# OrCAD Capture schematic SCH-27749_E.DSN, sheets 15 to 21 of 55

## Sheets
15 2V5 & PHY 1V8 Power: size C
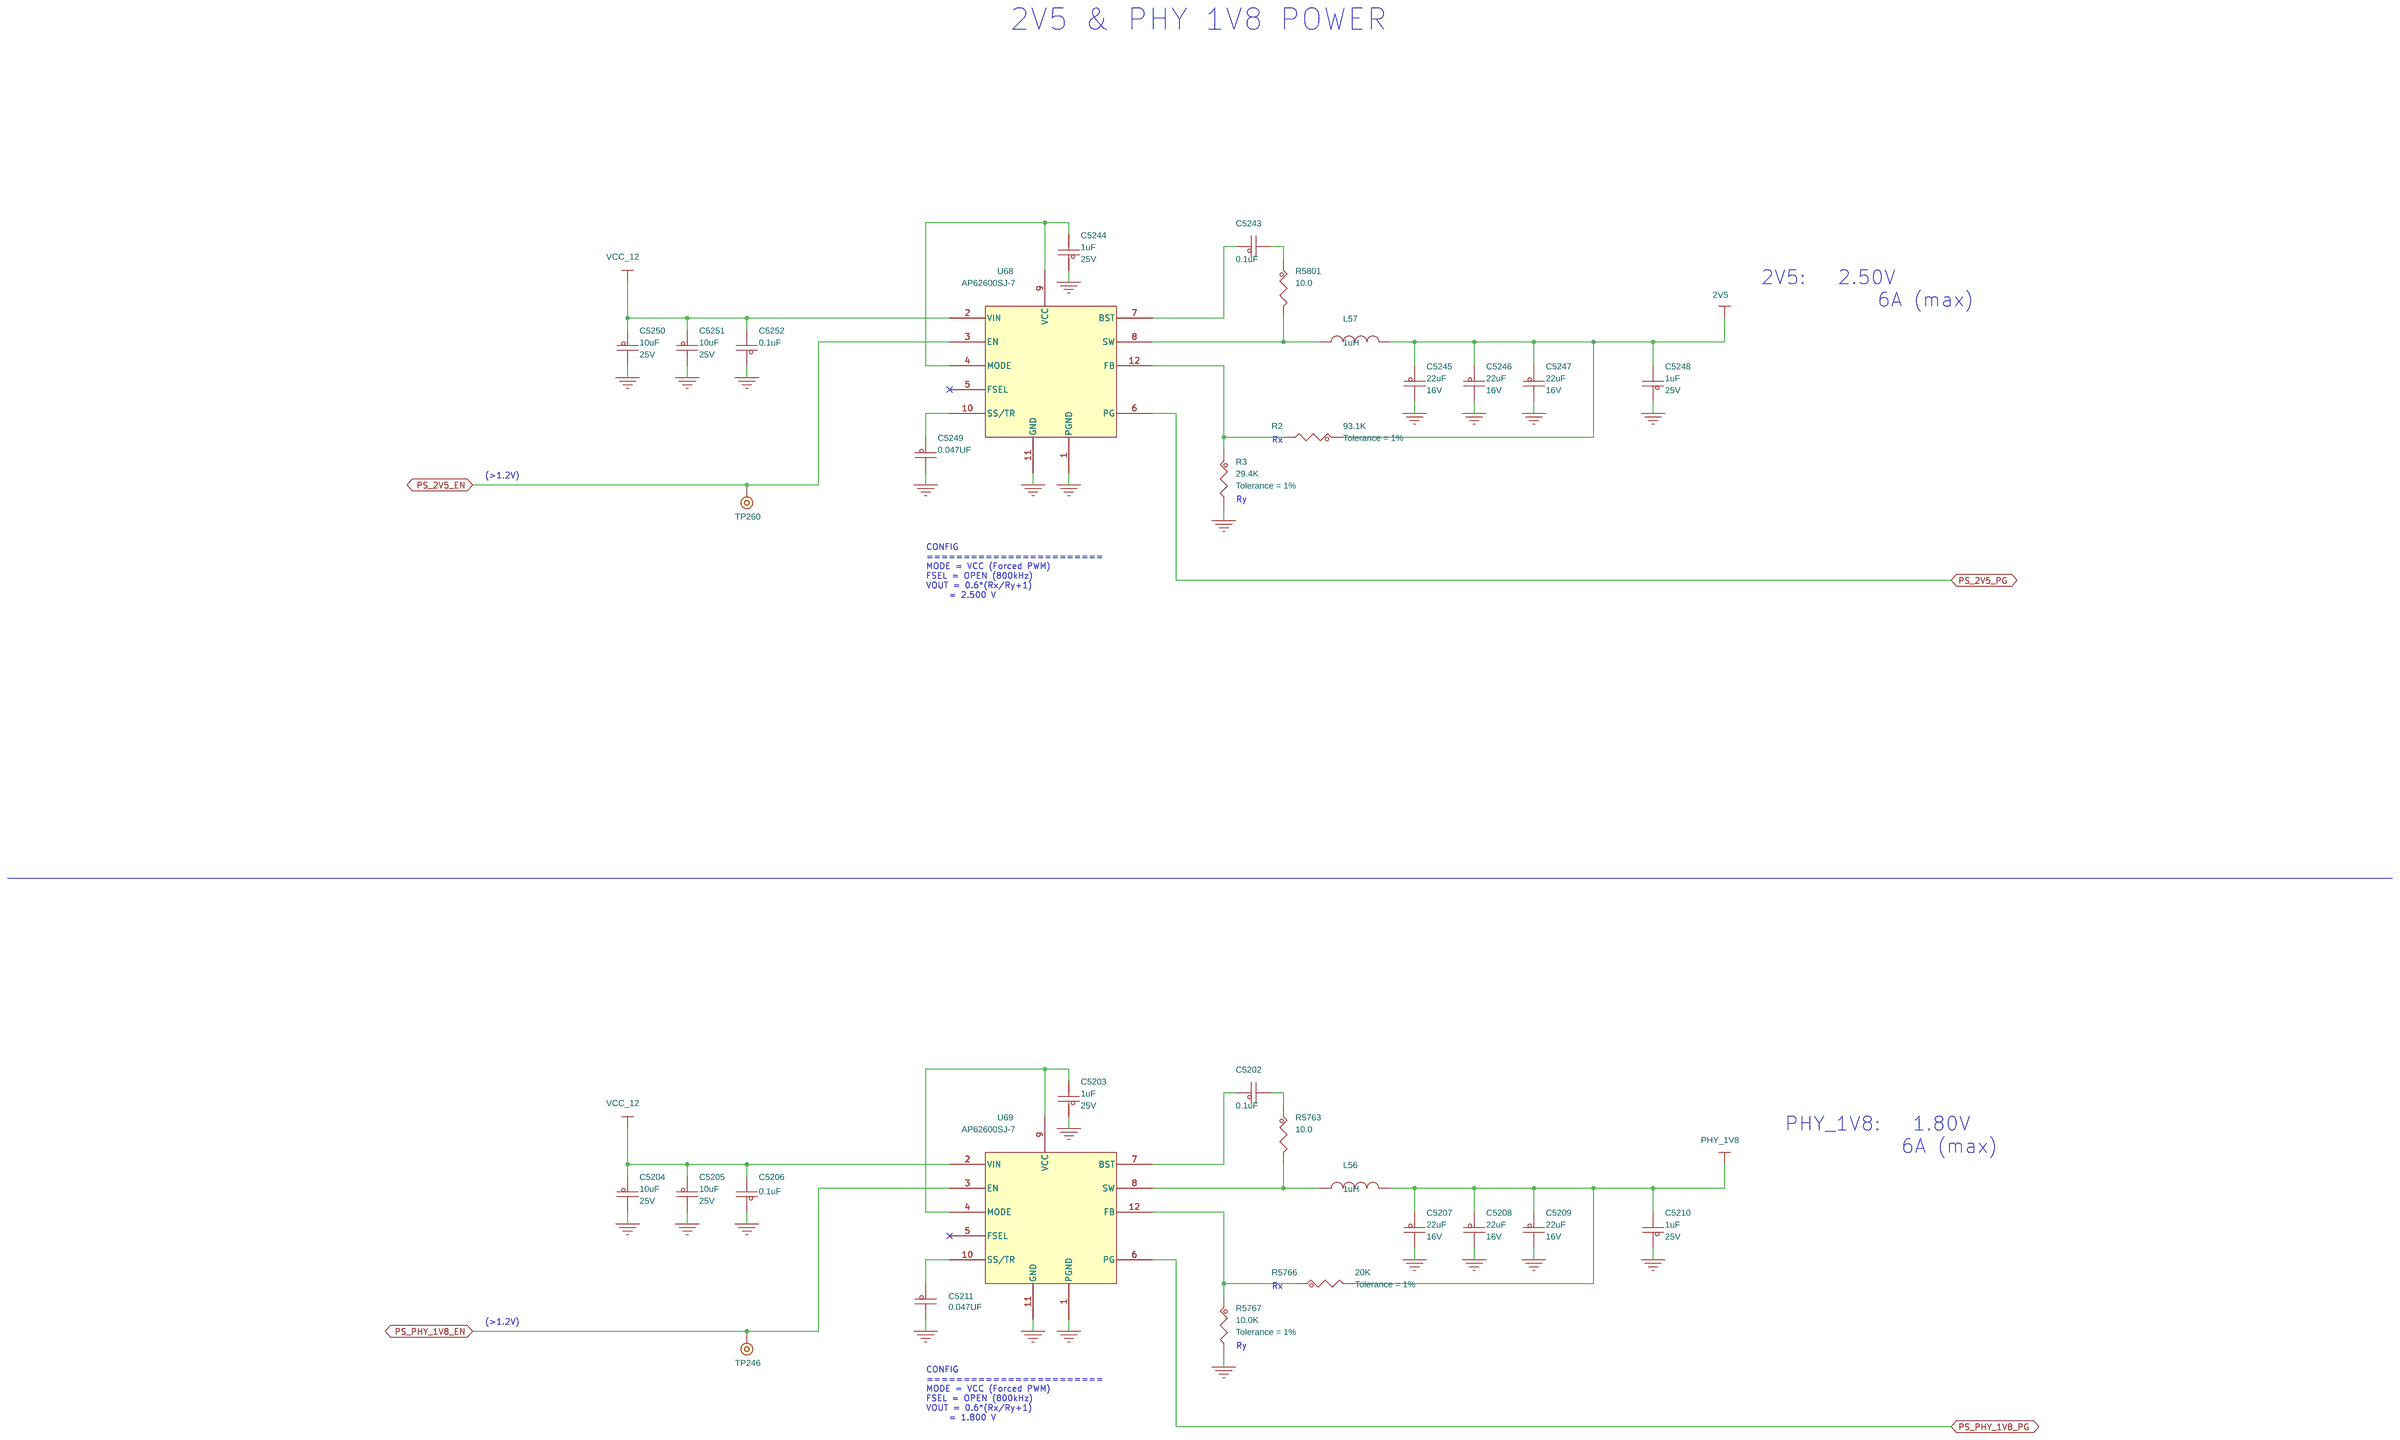
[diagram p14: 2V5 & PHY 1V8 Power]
16 Misc Power: size C
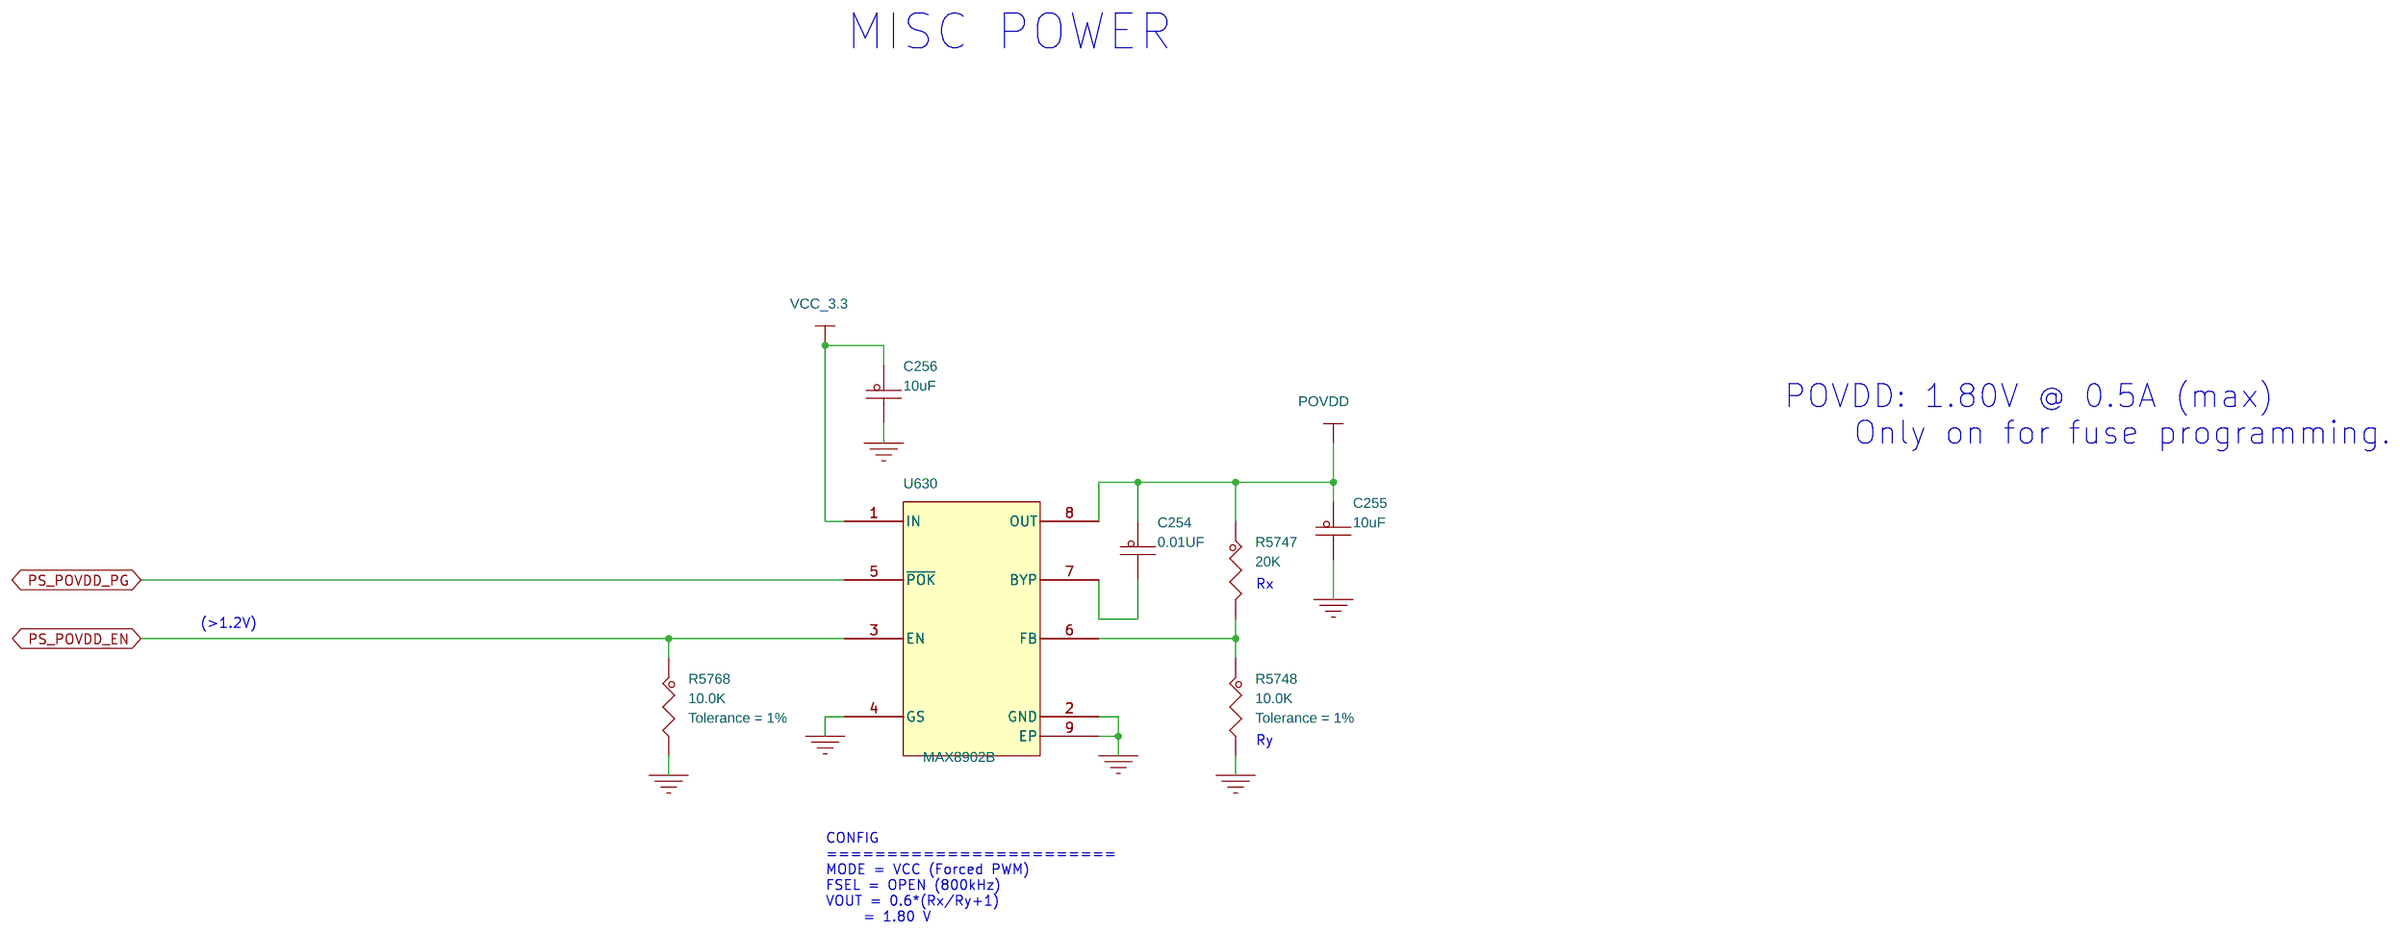
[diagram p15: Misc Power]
17 reserved
18 T4240 VDD Power: size C
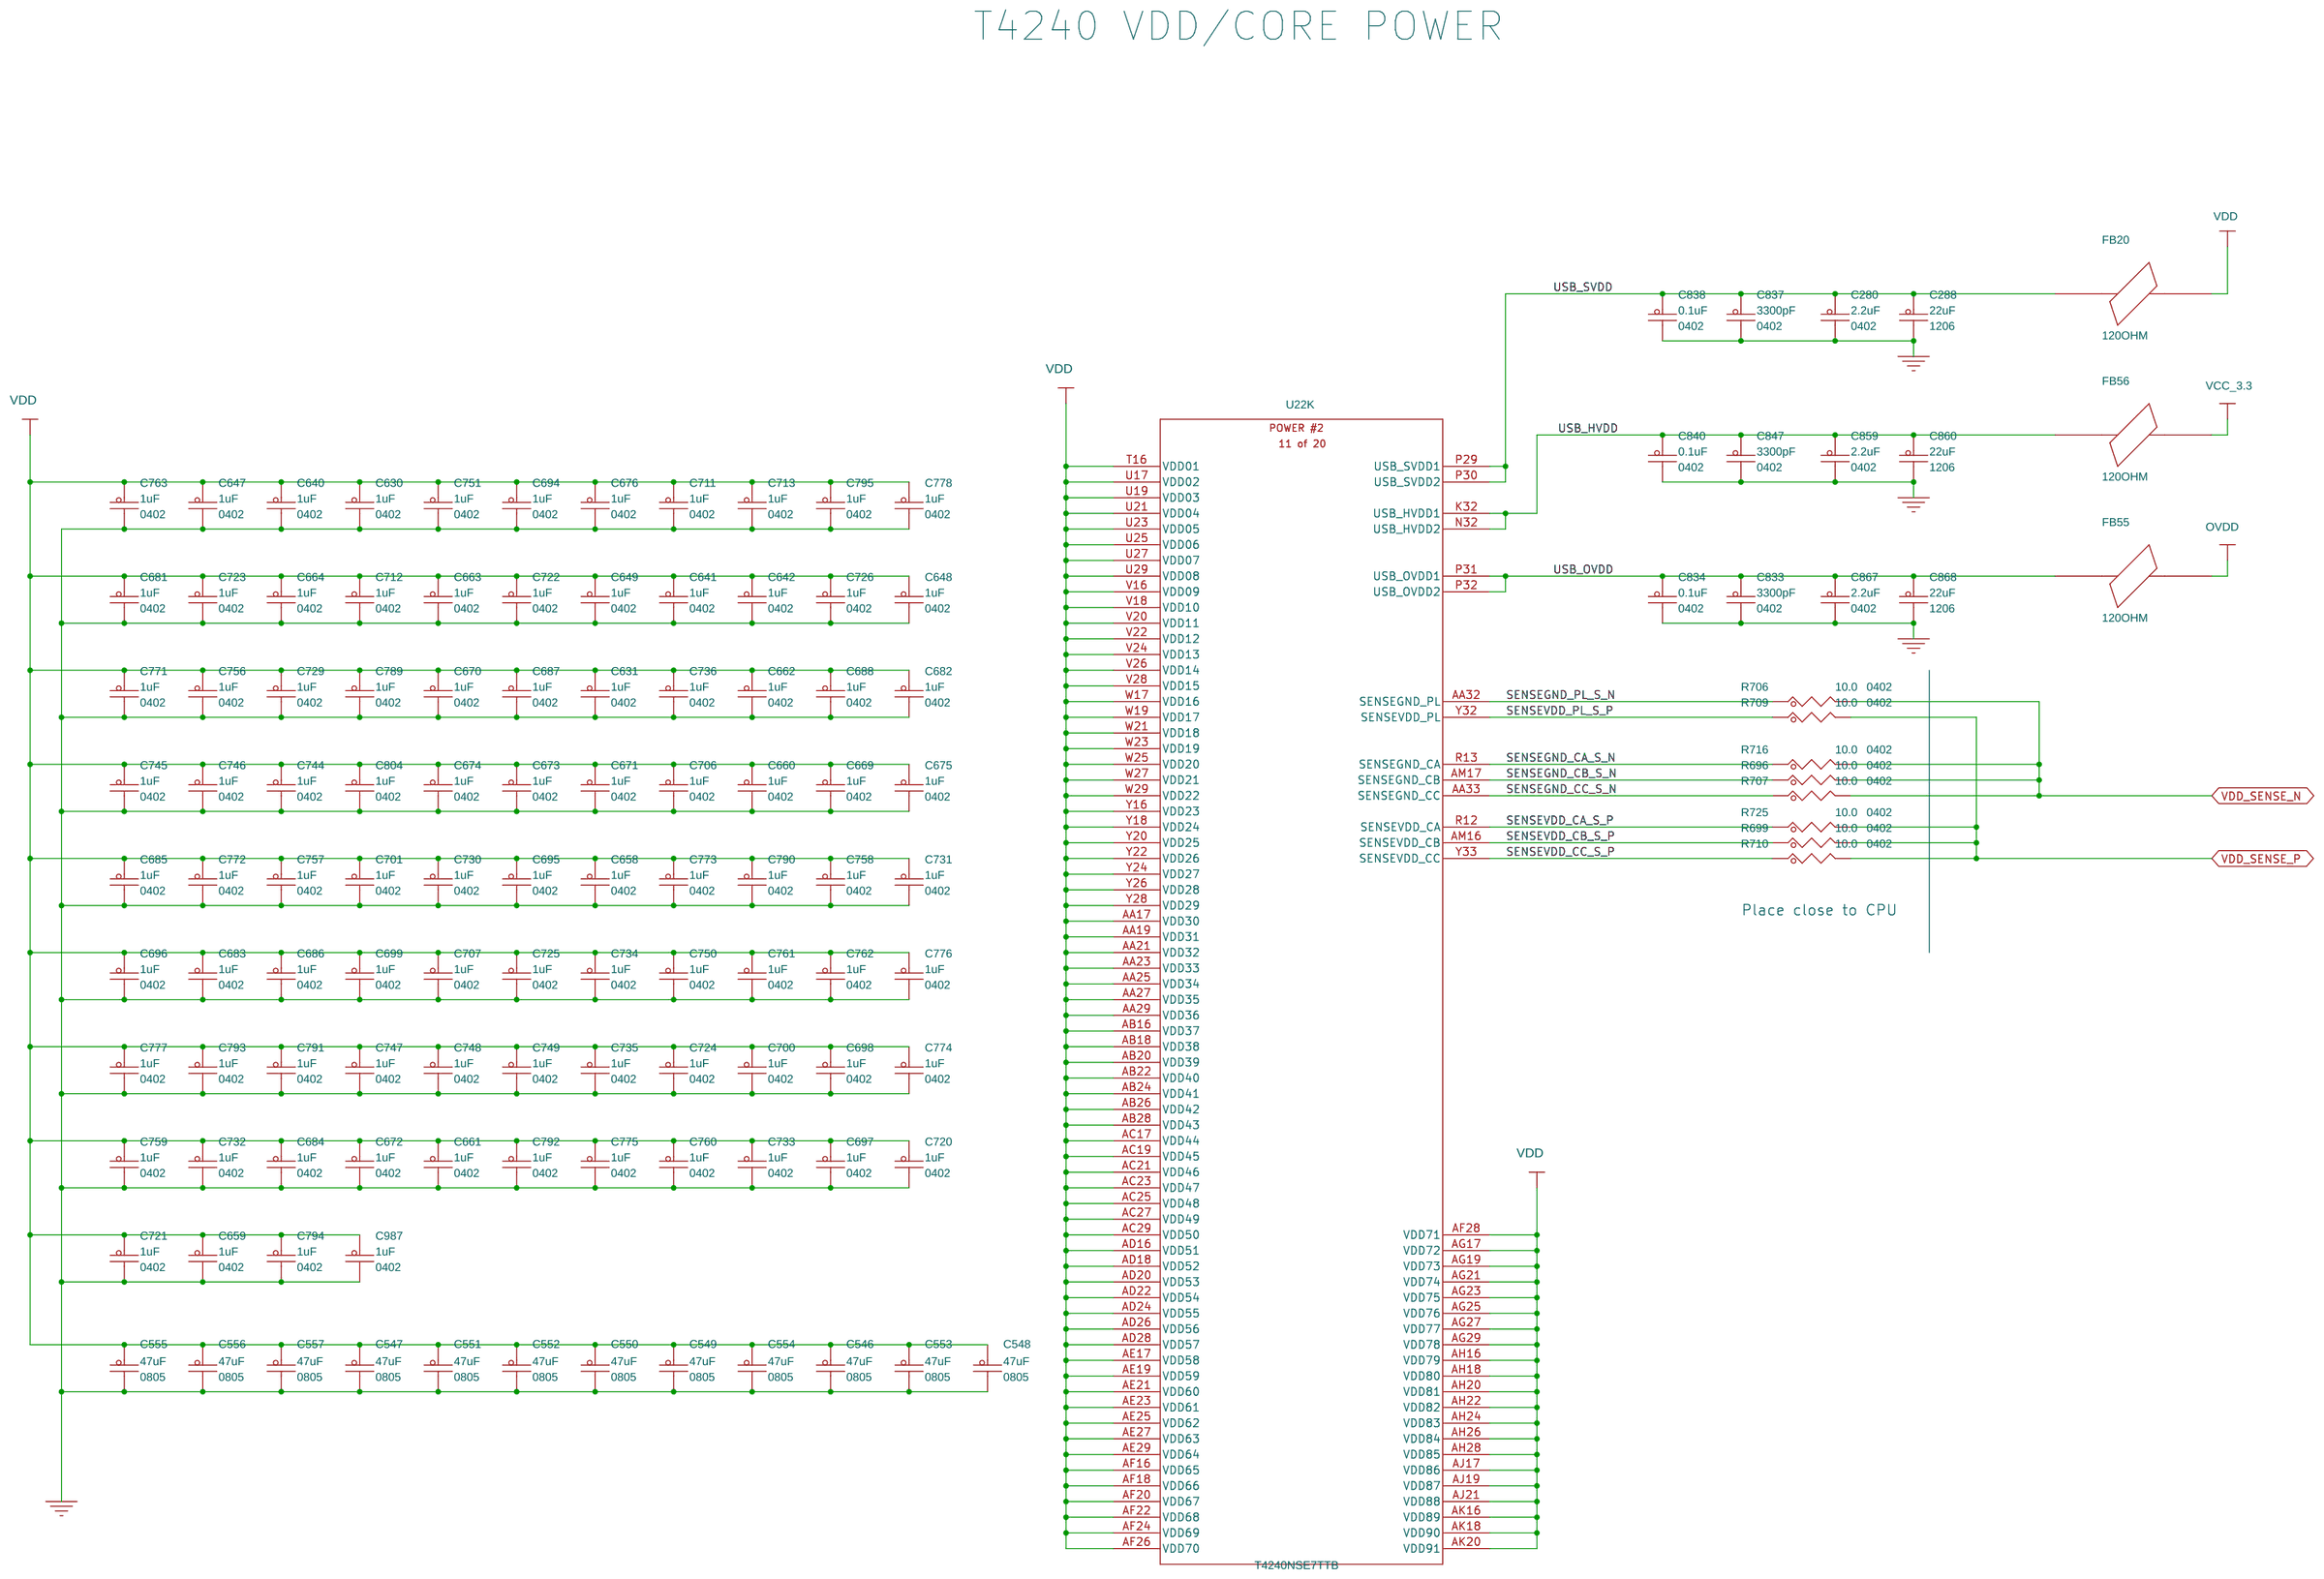
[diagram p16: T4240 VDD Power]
19 T4240 SVDD/XVDD Power: size C
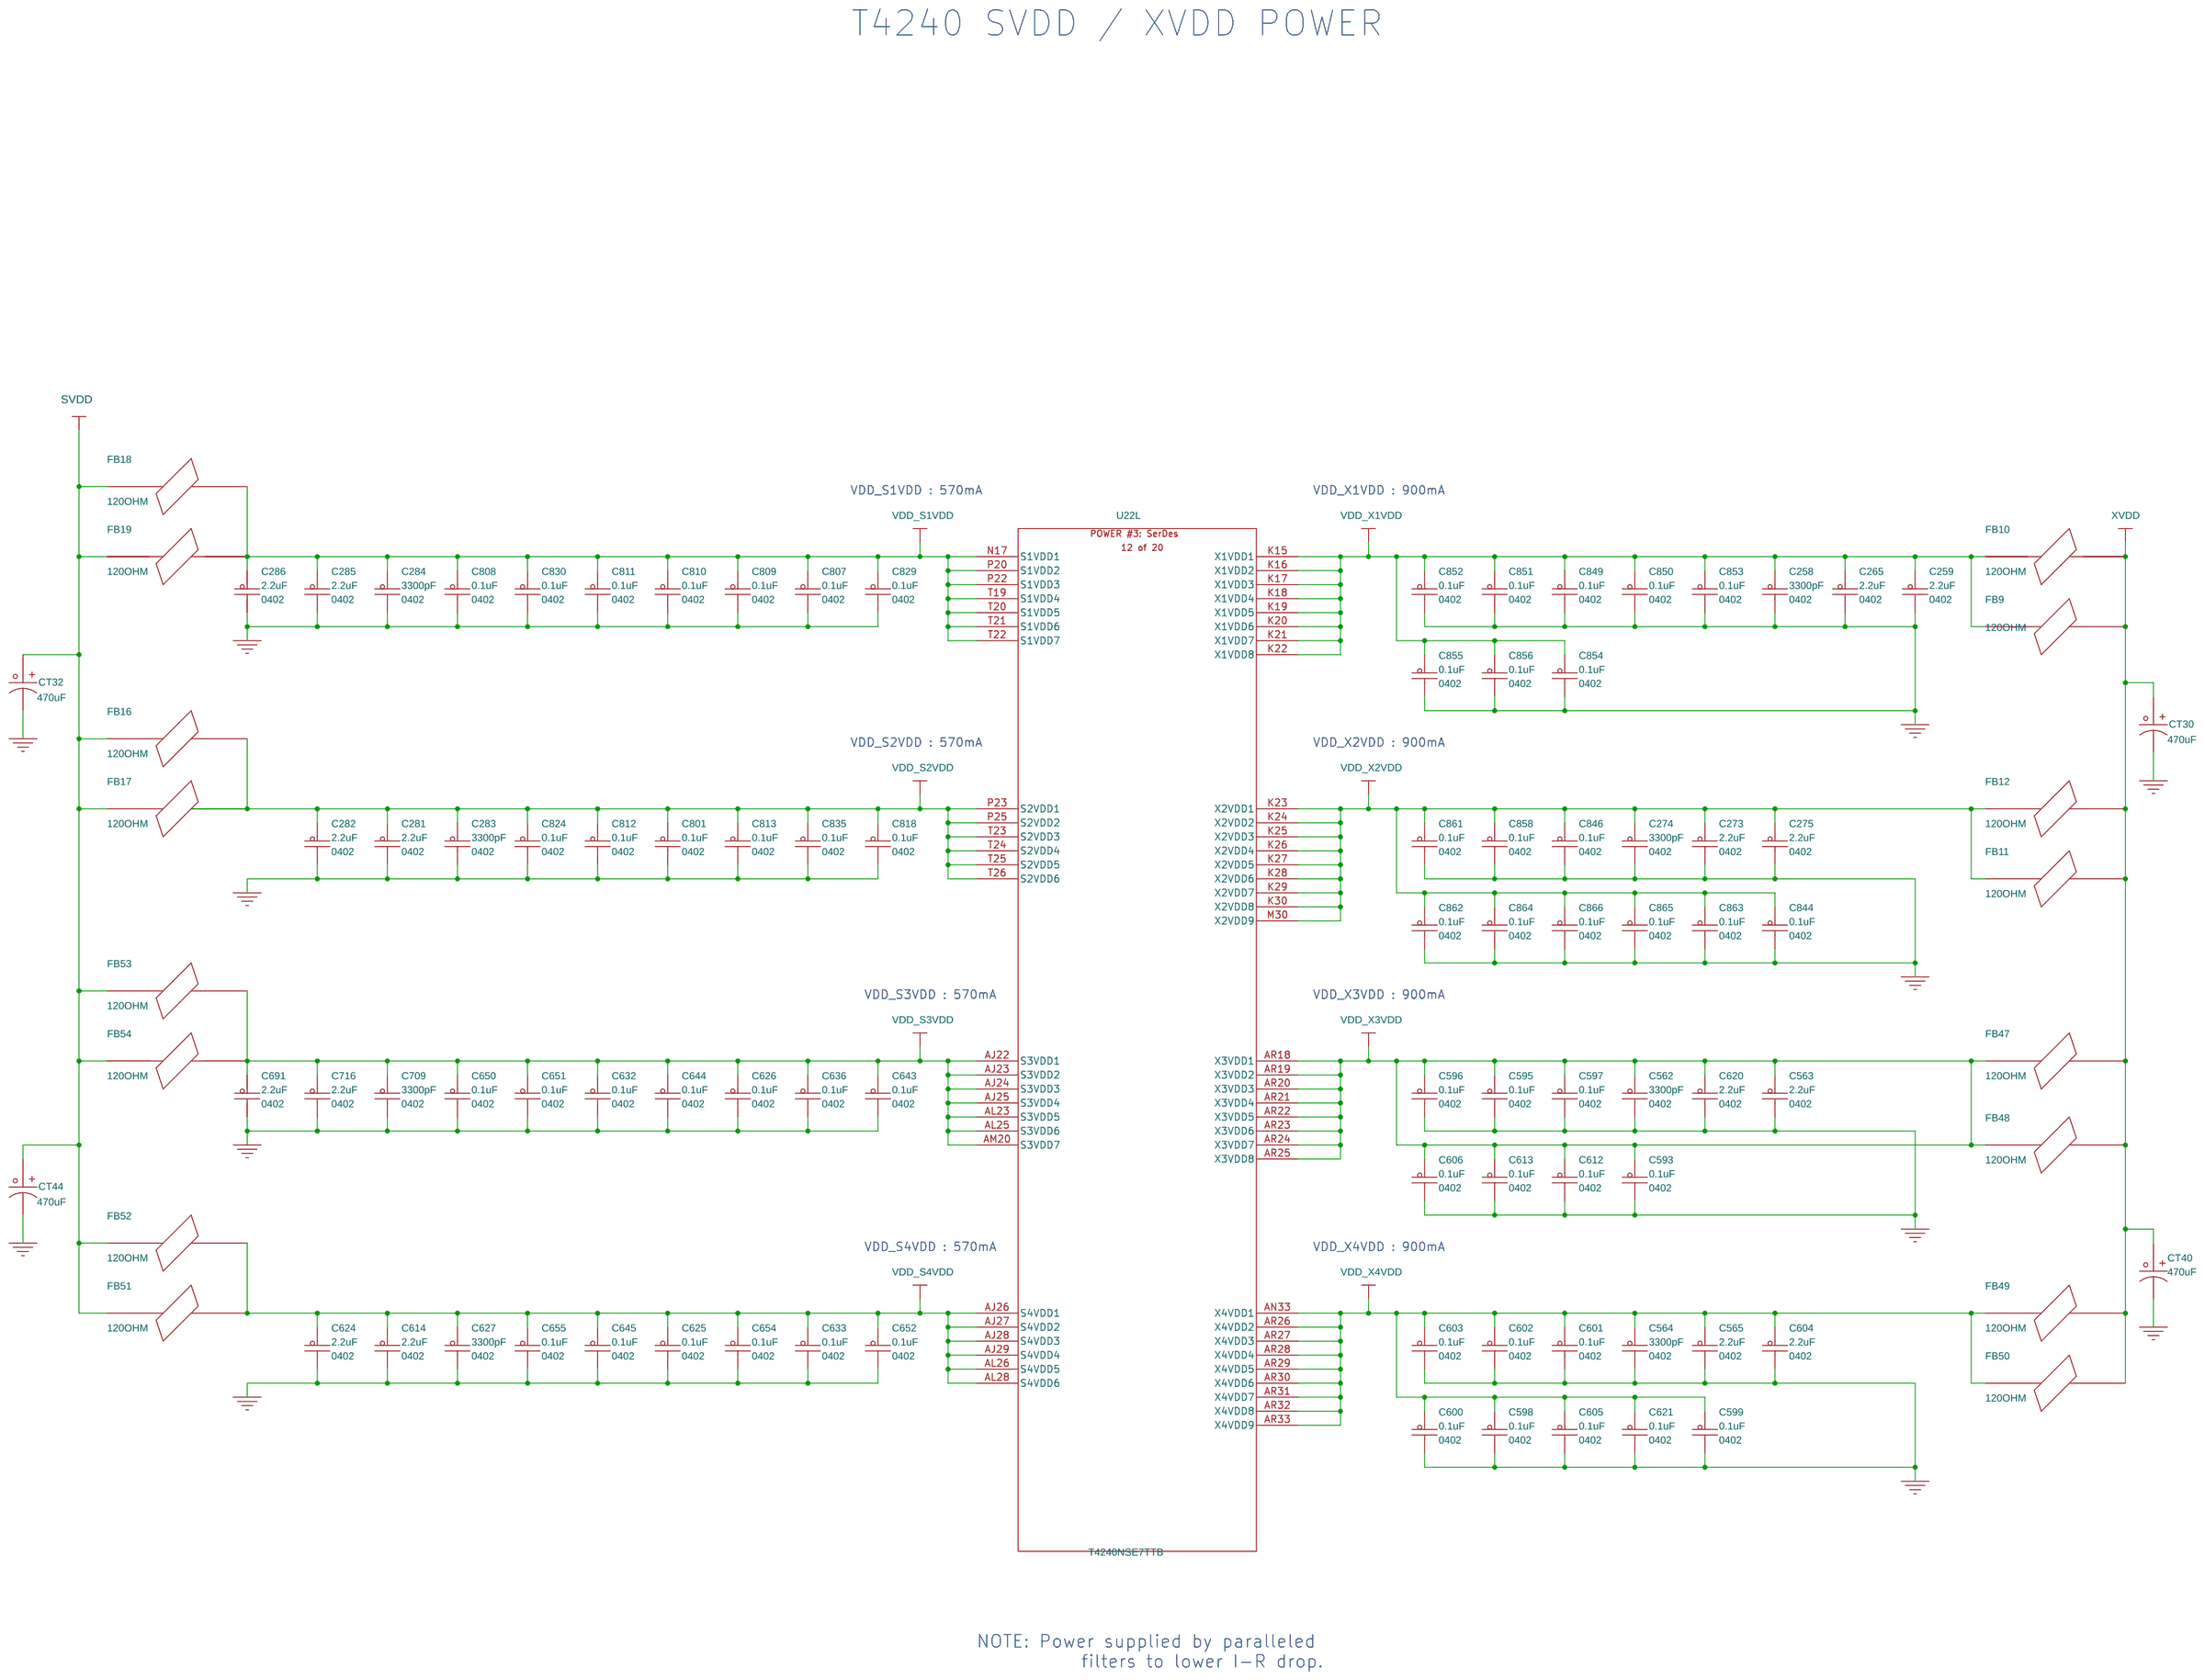
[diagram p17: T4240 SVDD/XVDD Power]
20 T4240 GVDD+Other Power: size C
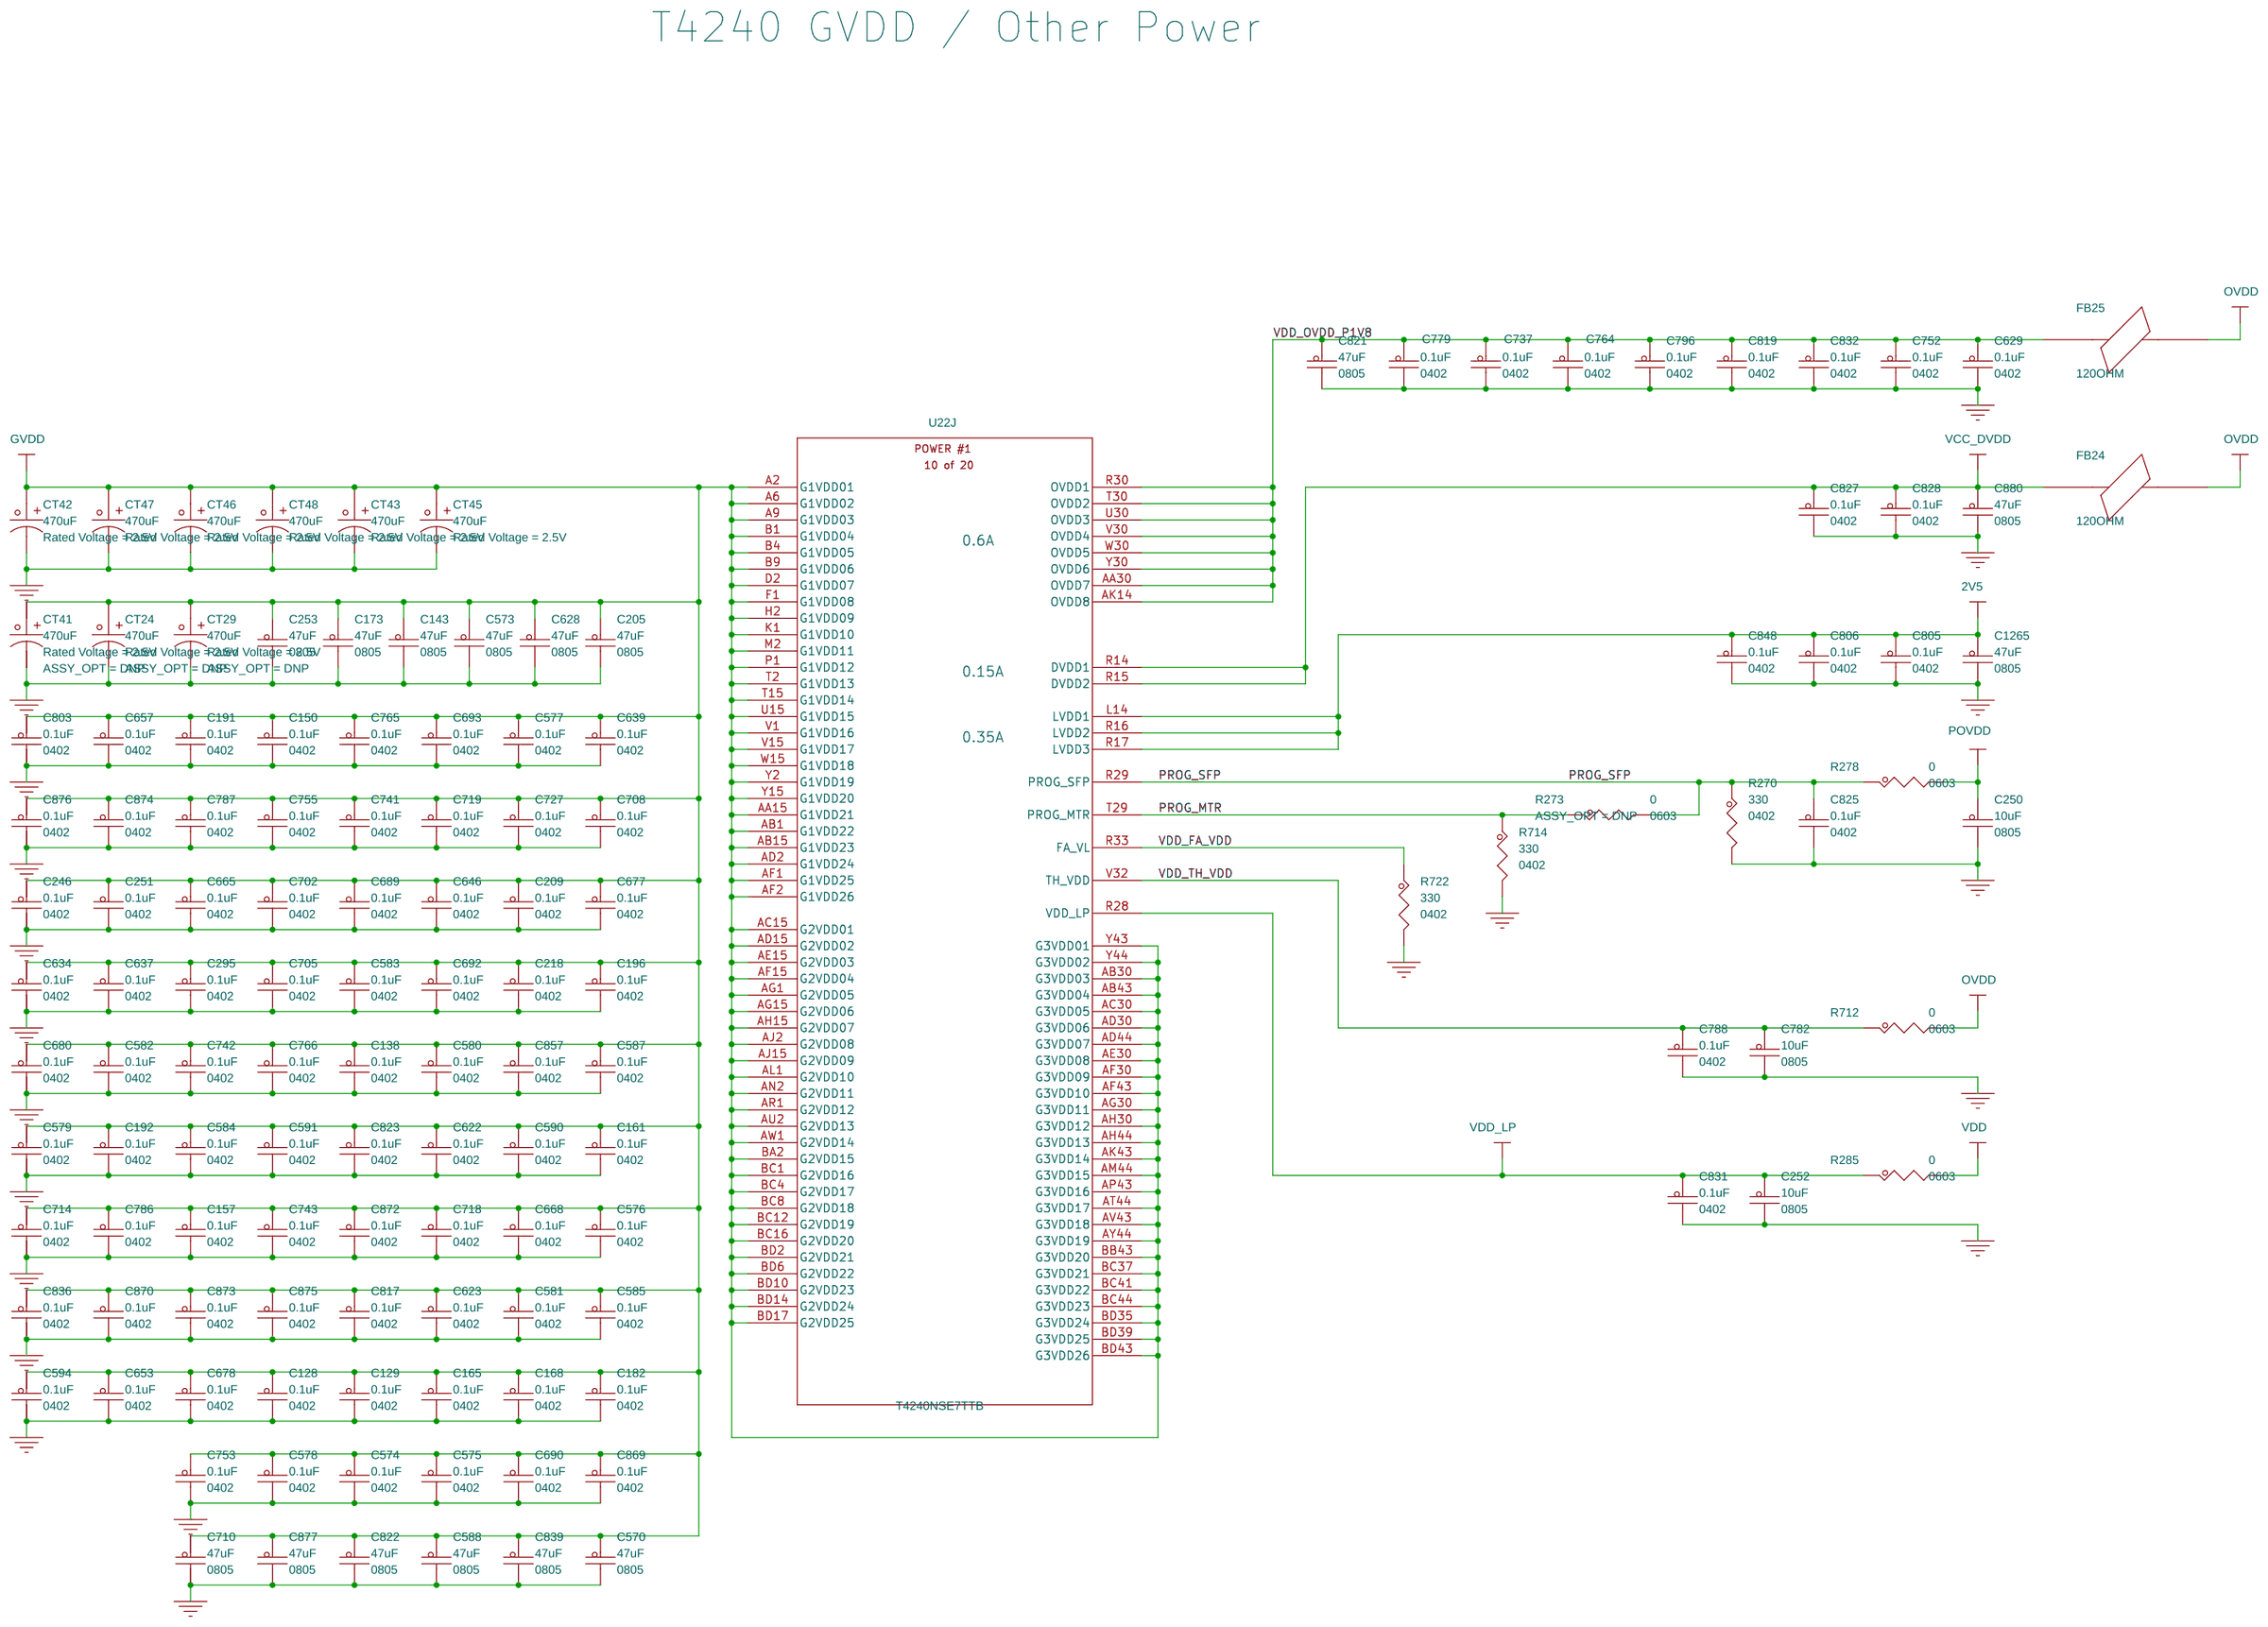
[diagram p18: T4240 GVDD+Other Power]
21 T4240 PLL Filters: size C
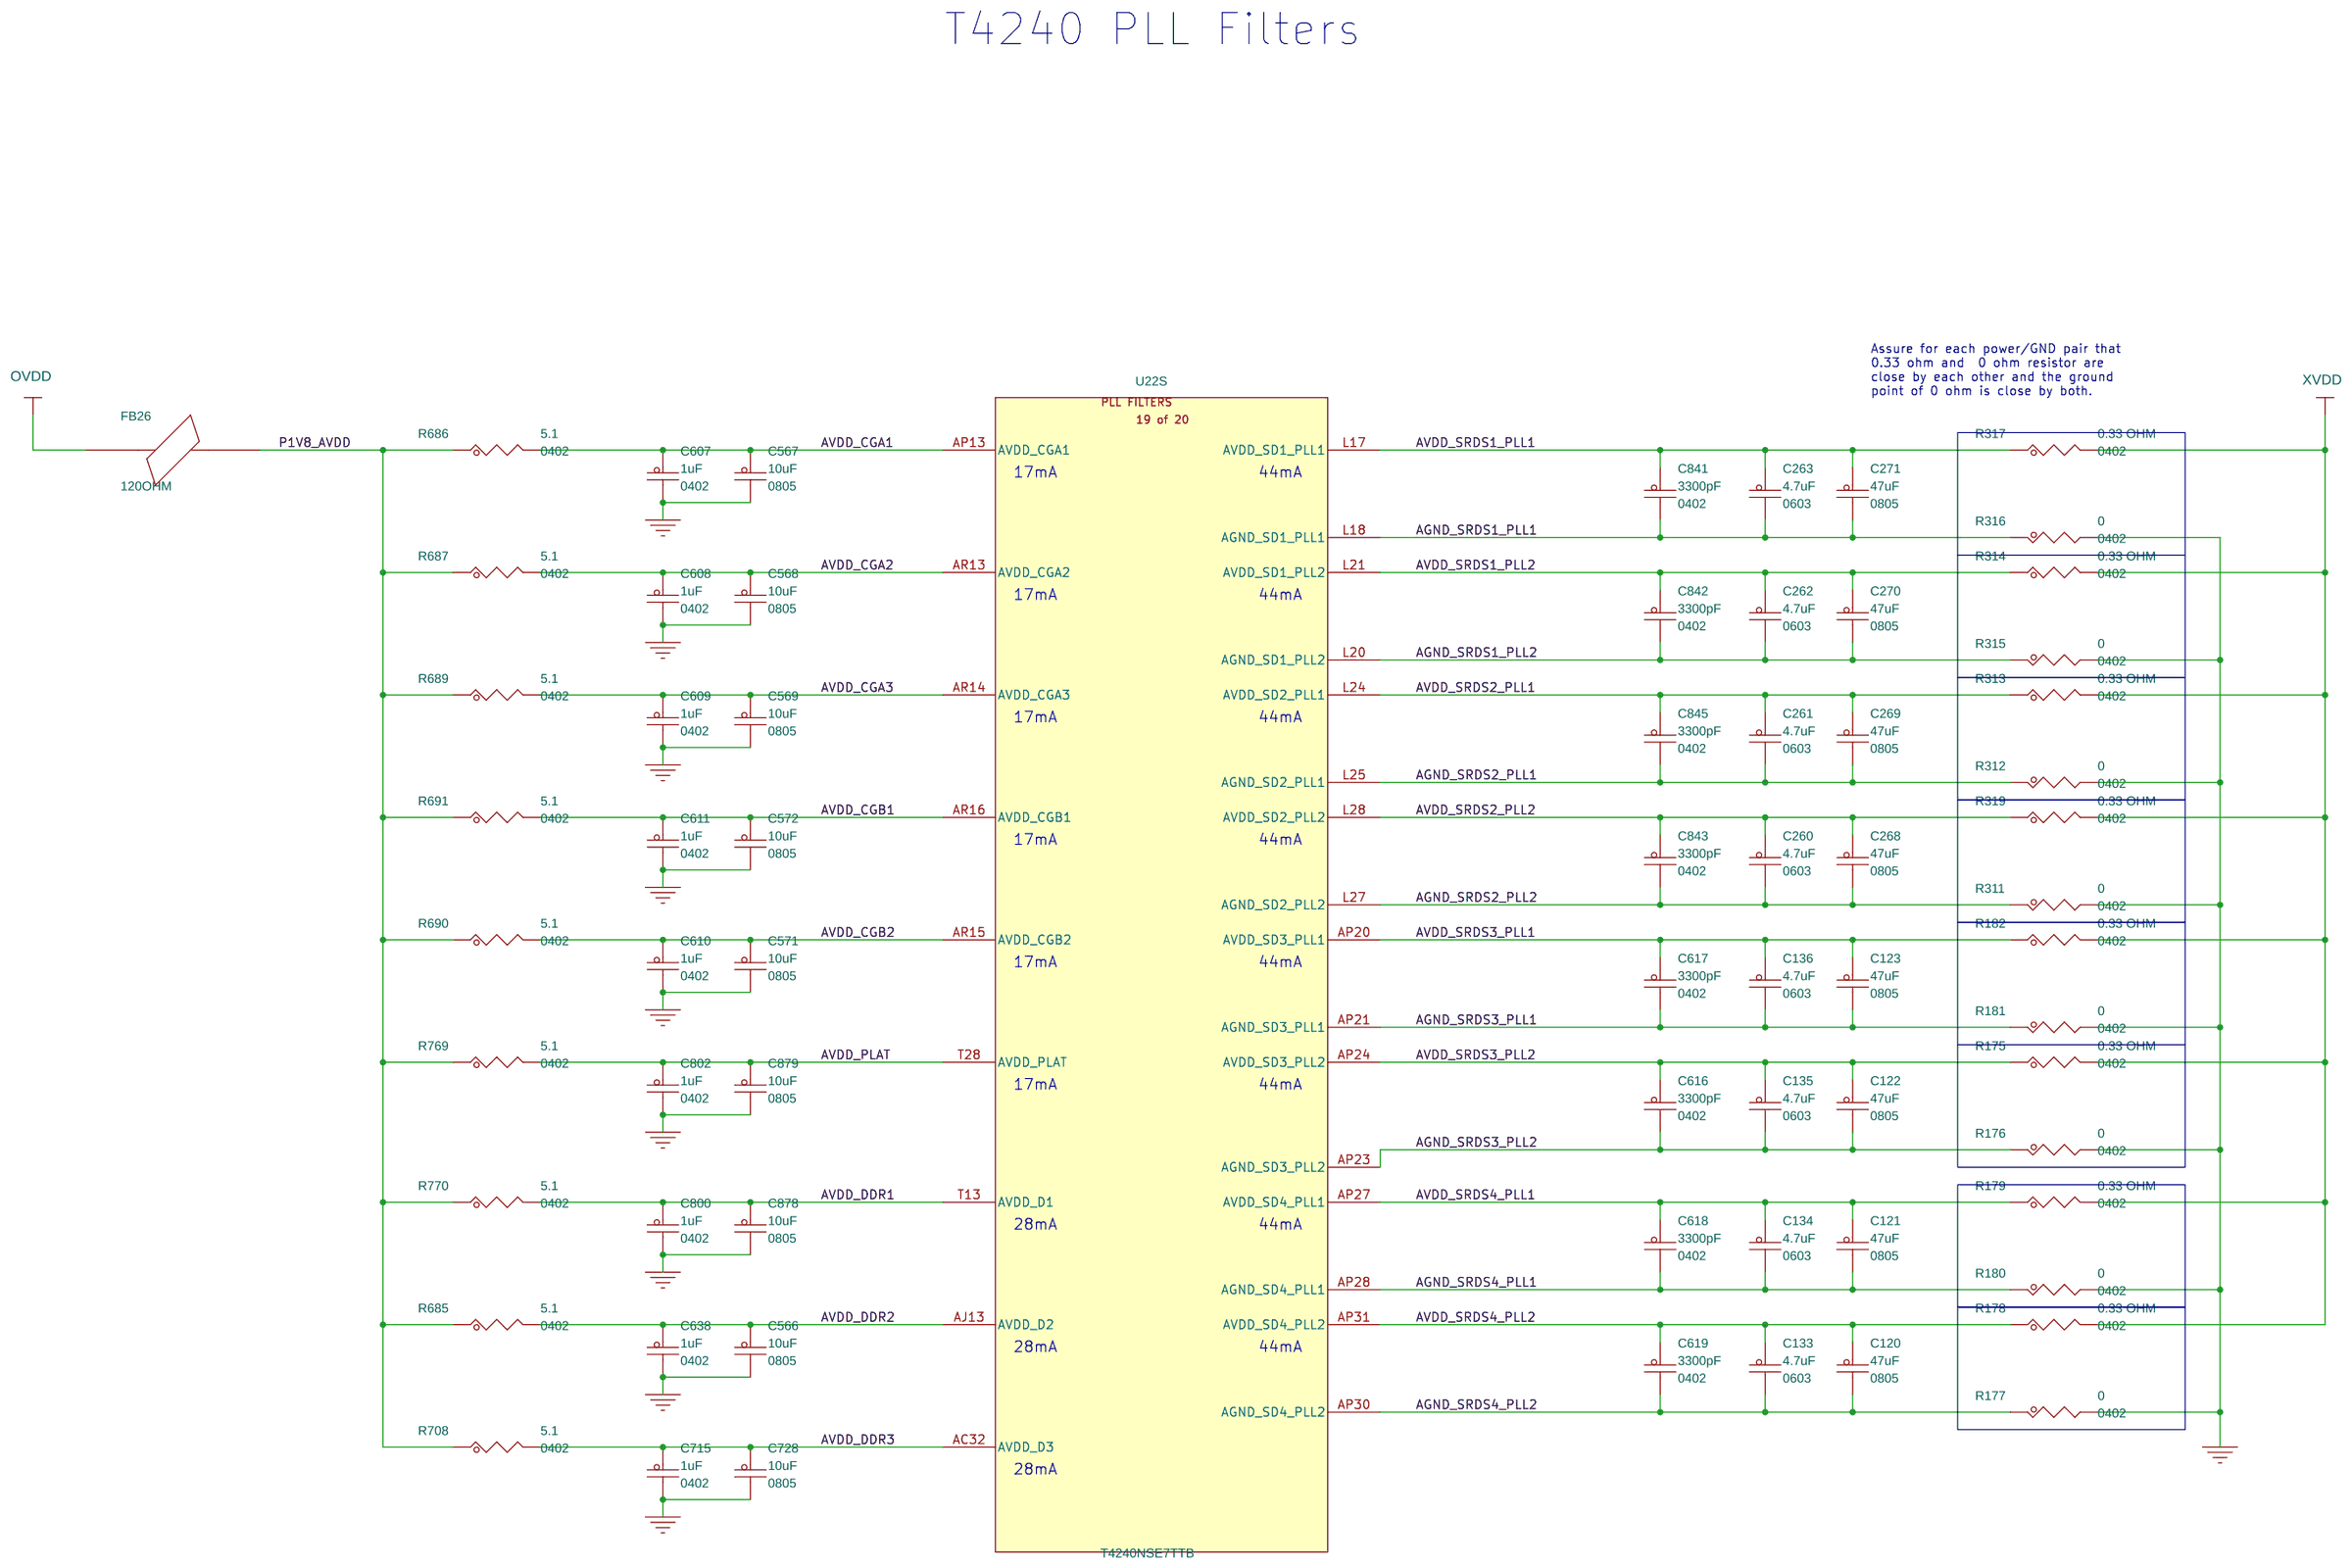
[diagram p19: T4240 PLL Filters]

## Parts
sheet 2V5 & PHY 1V8 Power
C5202  0.1uF  [CC0402_HD]
C5203  1uF  [CC0603_OV]
C5204  10uF  [CC1206_OV]
C5205  10uF  [CC1206_OV]
C5206  0.1uF  [CC0402_HD]
C5207  22uF  [1206_CC]
C5208  22uF  [1206_CC]
C5209  22uF  [1206_CC]
C5210  1uF  [CC0603_OV]
C5211  0.047UF  [CC0603_OV]
C5243  0.1uF  [CC0402_HD]
C5244  1uF  [CC0603_OV]
C5245  22uF  [1206_CC]
C5246  22uF  [1206_CC]
C5247  22uF  [1206_CC]
C5248  1uF  [CC0603_OV]
C5249  0.047UF  [CC0603_OV]
C5250  10uF  [CC1206_OV]
C5251  10uF  [CC1206_OV]
C5252  0.1uF  [CC0402_HD]
L56  1uH  [ind2_sq6p9_3_sm]
L57  1uH  [ind2_sq6p9_3_sm]
R2  93.1K  [RC0402_25]
R3  29.4K  [RC0402_25]
R5763  10.0  [RC0402_25]
R5766  20K  [RC0402_25]
R5767  10.0K  [RC0402_25]
R5801  10.0  [RC0402_25]
TP246  TPAD_020  [tpad_020_top]
TP260  TPAD_020  [tpad_020_top]
U68  AP62600SJ-7  [qfn12_0p5_2p05x3p05mm]
U69  AP62600SJ-7  [qfn12_0p5_2p05x3p05mm]
sheet Misc Power
C254  0.01UF  [CC0402_HD]
C255  10uF  [CC0603_OV]
C256  10uF  [CC0603_OV]
R5747  20K  [RC0402_25]
R5748  10.0K  [RC0402_25]
R5768  10.0K  [RC0402_25]
U630  MAX8902B  [tdfn8_1p98_2p10x2p10]
sheet T4240 DDR Controller #2
U22  T4240NSE7TTB  [BGA1932_1MM_45X45MM]  (sections A,B,C,D,E,F,G,H,I,J,K,L,M,N,O,P,Q,R,S,T)
sheet T4240 GVDD+Other Power
C128  0.1uF  [CC0402_HD]
C129  0.1uF  [CC0402_HD]
C138  0.1uF  [CC0402_HD]
C143  47uF  [CC0805_OV]
C150  0.1uF  [CC0402_HD]
C157  0.1uF  [CC0402_HD]
C161  0.1uF  [CC0402_HD]
C165  0.1uF  [CC0402_HD]
C168  0.1uF  [CC0402_HD]
C173  47uF  [CC0805_OV]
C182  0.1uF  [CC0402_HD]
C191  0.1uF  [CC0402_HD]
C192  0.1uF  [CC0402_HD]
C196  0.1uF  [CC0402_HD]
C205  47uF  [CC0805_OV]
C209  0.1uF  [CC0402_HD]
C218  0.1uF  [CC0402_HD]
C246  0.1uF  [CC0402_HD]
C250  10uF  [CC0603_OV]
C251  0.1uF  [CC0402_HD]
C252  10uF  [CC0603_OV]
C253  47uF  [CC0805_OV]
C295  0.1uF  [CC0402_HD]
C570  47uF  [CC0805_OV]
C573  47uF  [CC0805_OV]
C574  0.1uF  [CC0402_HD]
C575  0.1uF  [CC0402_HD]
C576  0.1uF  [CC0402_HD]
C577  0.1uF  [CC0402_HD]
C578  0.1uF  [CC0402_HD]
C579  0.1uF  [CC0402_HD]
C580  0.1uF  [CC0402_HD]
C581  0.1uF  [CC0402_HD]
C582  0.1uF  [CC0402_HD]
C583  0.1uF  [CC0402_HD]
C584  0.1uF  [CC0402_HD]
C585  0.1uF  [CC0402_HD]
C587  0.1uF  [CC0402_HD]
C588  47uF  [CC0805_OV]
C590  0.1uF  [CC0402_HD]
C591  0.1uF  [CC0402_HD]
C594  0.1uF  [CC0402_HD]
C622  0.1uF  [CC0402_HD]
C623  0.1uF  [CC0402_HD]
C628  47uF  [CC0805_OV]
C629  0.1uF  [CC0402_HD]
C634  0.1uF  [CC0402_HD]
C637  0.1uF  [CC0402_HD]
C639  0.1uF  [CC0402_HD]
C646  0.1uF  [CC0402_HD]
C653  0.1uF  [CC0402_HD]
C657  0.1uF  [CC0402_HD]
C665  0.1uF  [CC0402_HD]
C668  0.1uF  [CC0402_HD]
C677  0.1uF  [CC0402_HD]
C678  0.1uF  [CC0402_HD]
C680  0.1uF  [CC0402_HD]
C689  0.1uF  [CC0402_HD]
C690  0.1uF  [CC0402_HD]
C692  0.1uF  [CC0402_HD]
C693  0.1uF  [CC0402_HD]
C702  0.1uF  [CC0402_HD]
C705  0.1uF  [CC0402_HD]
C708  0.1uF  [CC0402_HD]
C710  47uF  [CC0805_OV]
C714  0.1uF  [CC0402_HD]
C718  0.1uF  [CC0402_HD]
C719  0.1uF  [CC0402_HD]
C727  0.1uF  [CC0402_HD]
C737  0.1uF  [CC0402_HD]
C741  0.1uF  [CC0402_HD]
C742  0.1uF  [CC0402_HD]
C743  0.1uF  [CC0402_HD]
C752  0.1uF  [CC0402_HD]
C753  0.1uF  [CC0402_HD]
C755  0.1uF  [CC0402_HD]
C764  0.1uF  [CC0402_HD]
C765  0.1uF  [CC0402_HD]
C766  0.1uF  [CC0402_HD]
C779  0.1uF  [CC0402_HD]
C782  10uF  [CC0603_OV]
C786  0.1uF  [CC0402_HD]
C787  0.1uF  [CC0402_HD]
C788  0.1uF  [CC0402_HD]
C796  0.1uF  [CC0402_HD]
C803  0.1uF  [CC0402_HD]
C805  0.1uF  [CC0402_HD]
C806  0.1uF  [CC0402_HD]
C817  0.1uF  [CC0402_HD]
C819  0.1uF  [CC0402_HD]
C821  47uF  [CC0805_OV]
C822  47uF  [CC0805_OV]
C823  0.1uF  [CC0402_HD]
C825  0.1uF  [CC0402_HD]
C827  0.1uF  [CC0402_HD]
C828  0.1uF  [CC0402_HD]
C831  0.1uF  [CC0402_HD]
C832  0.1uF  [CC0402_HD]
C836  0.1uF  [CC0402_HD]
C839  47uF  [CC0805_OV]
C848  0.1uF  [CC0402_HD]
C857  0.1uF  [CC0402_HD]
C869  0.1uF  [CC0402_HD]
C870  0.1uF  [CC0402_HD]
C872  0.1uF  [CC0402_HD]
C873  0.1uF  [CC0402_HD]
C874  0.1uF  [CC0402_HD]
C875  0.1uF  [CC0402_HD]
C876  0.1uF  [CC0402_HD]
C877  47uF  [CC0805_OV]
C880  47uF  [CC0805_OV]
C1265  47uF  [CC0805_OV]
CT24  470uF  [CC7343A]
CT29  470uF  [CC7343A]
CT41  470uF  [CC7343A]
CT42  470uF  [CC7343A]
CT43  470uF  [CC7343A]
CT45  470uF  [CC7343A]
CT46  470uF  [CC7343A]
CT47  470uF  [CC7343A]
CT48  470uF  [CC7343A]
FB24  120OHM  [IND_0603]
FB25  120OHM  [IND_0603]
R270  330  [RC0402_25]
R273  0  [RC0603_OV]
R278  0  [RC0603_OV]
R285  0  [RC0603_OV]
R712  0  [RC0603_OV]
R714  330  [RC0402_25]
R722  330  [RC0402_25]
sheet T4240 PLL Filters
C120  47uF  [CC0805_OV]
C121  47uF  [CC0805_OV]
C122  47uF  [CC0805_OV]
C123  47uF  [CC0805_OV]
C133  4.7uF  [CC0603_OV]
C134  4.7uF  [CC0603_OV]
C135  4.7uF  [CC0603_OV]
C136  4.7uF  [CC0603_OV]
C260  4.7uF  [CC0603_OV]
C261  4.7uF  [CC0603_OV]
C262  4.7uF  [CC0603_OV]
C263  4.7uF  [CC0603_OV]
C268  47uF  [CC0805_OV]
C269  47uF  [CC0805_OV]
C270  47uF  [CC0805_OV]
C271  47uF  [CC0805_OV]
C566  10uF  [CC0603_OV]
C567  10uF  [CC0603_OV]
C568  10uF  [CC0603_OV]
C569  10uF  [CC0603_OV]
C571  10uF  [CC0603_OV]
C572  10uF  [CC0603_OV]
C607  1uF  [CC0402_HD]
C608  1uF  [CC0402_HD]
C609  1uF  [CC0402_HD]
C610  1uF  [CC0402_HD]
C611  1uF  [CC0402_HD]
C616  3300pF  [CC0402_HD]
C617  3300pF  [CC0402_HD]
C618  3300pF  [CC0402_HD]
C619  3300pF  [CC0402_HD]
C638  1uF  [CC0402_HD]
C715  1uF  [CC0402_HD]
C728  10uF  [CC0603_OV]
C800  1uF  [CC0402_HD]
C802  1uF  [CC0402_HD]
C841  3300pF  [CC0402_HD]
C842  3300pF  [CC0402_HD]
C843  3300pF  [CC0402_HD]
C845  3300pF  [CC0402_HD]
C878  10uF  [CC0603_OV]
C879  10uF  [CC0603_OV]
FB26  120OHM  [IND_0603]
R175  0.33 OHM  [RC0402_25]
R176  0  [RC0402_25]
R177  0  [RC0402_25]
R178  0.33 OHM  [RC0402_25]
R179  0.33 OHM  [RC0402_25]
R180  0  [RC0402_25]
R181  0  [RC0402_25]
R182  0.33 OHM  [RC0402_25]
R311  0  [RC0402_25]
R312  0  [RC0402_25]
R313  0.33 OHM  [RC0402_25]
R314  0.33 OHM  [RC0402_25]
R315  0  [RC0402_25]
R316  0  [RC0402_25]
R317  0.33 OHM  [RC0402_25]
R319  0.33 OHM  [RC0402_25]
R685  5.1  [RC0402_25]
R686  5.1  [RC0402_25]
R687  5.1  [RC0402_25]
R689  5.1  [RC0402_25]
R690  5.1  [RC0402_25]
R691  5.1  [RC0402_25]
R708  5.1  [RC0402_25]
R769  5.1  [RC0402_25]
R770  5.1  [RC0402_25]
sheet T4240 SVDD/XVDD Power
C258  3300pF  [CC0402_HD]
C259  2.2uF  [CC0402_HD]
C265  2.2uF  [CC0402_HD]
C273  2.2uF  [CC0402_HD]
C274  3300pF  [CC0402_HD]
C275  2.2uF  [CC0402_HD]
C281  2.2uF  [CC0402_HD]
C282  2.2uF  [CC0402_HD]
C283  3300pF  [CC0402_HD]
C284  3300pF  [CC0402_HD]
C285  2.2uF  [CC0402_HD]
C286  2.2uF  [CC0402_HD]
C562  3300pF  [CC0402_HD]
C563  2.2uF  [CC0402_HD]
C564  3300pF  [CC0402_HD]
C565  2.2uF  [CC0402_HD]
C593  0.1uF  [CC0402_HD]
C595  0.1uF  [CC0402_HD]
C596  0.1uF  [CC0402_HD]
C597  0.1uF  [CC0402_HD]
C598  0.1uF  [CC0402_HD]
C599  0.1uF  [CC0402_HD]
C600  0.1uF  [CC0402_HD]
C601  0.1uF  [CC0402_HD]
C602  0.1uF  [CC0402_HD]
C603  0.1uF  [CC0402_HD]
C604  2.2uF  [CC0402_HD]
C605  0.1uF  [CC0402_HD]
C606  0.1uF  [CC0402_HD]
C612  0.1uF  [CC0402_HD]
C613  0.1uF  [CC0402_HD]
C614  2.2uF  [CC0402_HD]
C620  2.2uF  [CC0402_HD]
C621  0.1uF  [CC0402_HD]
C624  2.2uF  [CC0402_HD]
C625  0.1uF  [CC0402_HD]
C626  0.1uF  [CC0402_HD]
C627  3300pF  [CC0402_HD]
C632  0.1uF  [CC0402_HD]
C633  0.1uF  [CC0402_HD]
C636  0.1uF  [CC0402_HD]
C643  0.1uF  [CC0402_HD]
C644  0.1uF  [CC0402_HD]
C645  0.1uF  [CC0402_HD]
C650  0.1uF  [CC0402_HD]
C651  0.1uF  [CC0402_HD]
C652  0.1uF  [CC0402_HD]
C654  0.1uF  [CC0402_HD]
C655  0.1uF  [CC0402_HD]
C691  2.2uF  [CC0402_HD]
C709  3300pF  [CC0402_HD]
C716  2.2uF  [CC0402_HD]
C801  0.1uF  [CC0402_HD]
C807  0.1uF  [CC0402_HD]
C808  0.1uF  [CC0402_HD]
C809  0.1uF  [CC0402_HD]
C810  0.1uF  [CC0402_HD]
C811  0.1uF  [CC0402_HD]
C812  0.1uF  [CC0402_HD]
C813  0.1uF  [CC0402_HD]
C818  0.1uF  [CC0402_HD]
C824  0.1uF  [CC0402_HD]
C829  0.1uF  [CC0402_HD]
C830  0.1uF  [CC0402_HD]
C835  0.1uF  [CC0402_HD]
C844  0.1uF  [CC0402_HD]
C846  0.1uF  [CC0402_HD]
C849  0.1uF  [CC0402_HD]
C850  0.1uF  [CC0402_HD]
C851  0.1uF  [CC0402_HD]
C852  0.1uF  [CC0402_HD]
C853  0.1uF  [CC0402_HD]
C854  0.1uF  [CC0402_HD]
C855  0.1uF  [CC0402_HD]
C856  0.1uF  [CC0402_HD]
C858  0.1uF  [CC0402_HD]
C861  0.1uF  [CC0402_HD]
C862  0.1uF  [CC0402_HD]
C863  0.1uF  [CC0402_HD]
C864  0.1uF  [CC0402_HD]
C865  0.1uF  [CC0402_HD]
C866  0.1uF  [CC0402_HD]
CT30  470uF  [CC7343A]
CT32  470uF  [CC7343A]
CT40  470uF  [CC7343A]
CT44  470uF  [CC7343A]
FB9  120OHM  [IND_0603]
FB10  120OHM  [IND_0603]
FB11  120OHM  [IND_0603]
FB12  120OHM  [IND_0603]
FB16  120OHM  [IND_0603]
FB17  120OHM  [IND_0603]
FB18  120OHM  [IND_0603]
FB19  120OHM  [IND_0603]
FB47  120OHM  [IND_0603]
FB48  120OHM  [IND_0603]
FB49  120OHM  [IND_0603]
FB50  120OHM  [IND_0603]
FB51  120OHM  [IND_0603]
FB52  120OHM  [IND_0603]
FB53  120OHM  [IND_0603]
FB54  120OHM  [IND_0603]
sheet T4240 VDD Power
C280  2.2uF  [CC0402_HD]
C288  22uF  [1206_CC]
C546  47uF  [CC0805_OV]
C547  47uF  [CC0805_OV]
C548  47uF  [CC0805_OV]
C549  47uF  [CC0805_OV]
C550  47uF  [CC0805_OV]
C551  47uF  [CC0805_OV]
C552  47uF  [CC0805_OV]
C553  47uF  [CC0805_OV]
C554  47uF  [CC0805_OV]
C555  47uF  [CC0805_OV]
C556  47uF  [CC0805_OV]
C557  47uF  [CC0805_OV]
C630  1uF  [CC0402_HD]
C631  1uF  [CC0402_HD]
C640  1uF  [CC0402_HD]
C641  1uF  [CC0402_HD]
C642  1uF  [CC0402_HD]
C647  1uF  [CC0402_HD]
C648  1uF  [CC0402_HD]
C649  1uF  [CC0402_HD]
C658  1uF  [CC0402_HD]
C659  1uF  [CC0402_HD]
C660  1uF  [CC0402_HD]
C661  1uF  [CC0402_HD]
C662  1uF  [CC0402_HD]
C663  1uF  [CC0402_HD]
C664  1uF  [CC0402_HD]
C669  1uF  [CC0402_HD]
C670  1uF  [CC0402_HD]
C671  1uF  [CC0402_HD]
C672  1uF  [CC0402_HD]
C673  1uF  [CC0402_HD]
C674  1uF  [CC0402_HD]
C675  1uF  [CC0402_HD]
C676  1uF  [CC0402_HD]
C681  1uF  [CC0402_HD]
C682  1uF  [CC0402_HD]
C683  1uF  [CC0402_HD]
C684  1uF  [CC0402_HD]
C685  1uF  [CC0402_HD]
C686  1uF  [CC0402_HD]
C687  1uF  [CC0402_HD]
C688  1uF  [CC0402_HD]
C694  1uF  [CC0402_HD]
C695  1uF  [CC0402_HD]
C696  1uF  [CC0402_HD]
C697  1uF  [CC0402_HD]
C698  1uF  [CC0402_HD]
C699  1uF  [CC0402_HD]
C700  1uF  [CC0402_HD]
C701  1uF  [CC0402_HD]
C706  1uF  [CC0402_HD]
C707  1uF  [CC0402_HD]
C711  1uF  [CC0402_HD]
C712  1uF  [CC0402_HD]
C713  1uF  [CC0402_HD]
C720  1uF  [CC0402_HD]
C721  1uF  [CC0402_HD]
C722  1uF  [CC0402_HD]
C723  1uF  [CC0402_HD]
C724  1uF  [CC0402_HD]
C725  1uF  [CC0402_HD]
C726  1uF  [CC0402_HD]
C729  1uF  [CC0402_HD]
C730  1uF  [CC0402_HD]
C731  1uF  [CC0402_HD]
C732  1uF  [CC0402_HD]
C733  1uF  [CC0402_HD]
C734  1uF  [CC0402_HD]
C735  1uF  [CC0402_HD]
C736  1uF  [CC0402_HD]
C744  1uF  [CC0402_HD]
C745  1uF  [CC0402_HD]
C746  1uF  [CC0402_HD]
C747  1uF  [CC0402_HD]
C748  1uF  [CC0402_HD]
C749  1uF  [CC0402_HD]
C750  1uF  [CC0402_HD]
C751  1uF  [CC0402_HD]
C756  1uF  [CC0402_HD]
C757  1uF  [CC0402_HD]
C758  1uF  [CC0402_HD]
C759  1uF  [CC0402_HD]
C760  1uF  [CC0402_HD]
C761  1uF  [CC0402_HD]
C762  1uF  [CC0402_HD]
C763  1uF  [CC0402_HD]
C771  1uF  [CC0402_HD]
C772  1uF  [CC0402_HD]
C773  1uF  [CC0402_HD]
C774  1uF  [CC0402_HD]
C775  1uF  [CC0402_HD]
C776  1uF  [CC0402_HD]
C777  1uF  [CC0402_HD]
C778  1uF  [CC0402_HD]
C789  1uF  [CC0402_HD]
C790  1uF  [CC0402_HD]
C791  1uF  [CC0402_HD]
C792  1uF  [CC0402_HD]
C793  1uF  [CC0402_HD]
C794  1uF  [CC0402_HD]
C795  1uF  [CC0402_HD]
C804  1uF  [CC0402_HD]
C833  3300pF  [CC0402_HD]
C834  0.1uF  [CC0402_HD]
C837  3300pF  [CC0402_HD]
C838  0.1uF  [CC0402_HD]
C840  0.1uF  [CC0402_HD]
C847  3300pF  [CC0402_HD]
C859  2.2uF  [CC0402_HD]
C860  22uF  [1206_CC]
C867  2.2uF  [CC0402_HD]
C868  22uF  [1206_CC]
C987  1uF  [CC0402_HD]
FB20  120OHM  [IND_0603]
FB55  120OHM  [IND_0603]
FB56  120OHM  [IND_0603]
R696  10.0  [RC0402_25]
R699  10.0  [RC0402_25]
R706  10.0  [RC0402_25]
R707  10.0  [RC0402_25]
R709  10.0  [RC0402_25]
R710  10.0  [RC0402_25]
R716  10.0  [RC0402_25]
R725  10.0  [RC0402_25]

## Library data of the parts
C5202 C5206 C5243 C5252 = CAP_NP: CAP CER 0.1uF 16V 10% X7R AEC-Q200 0402; AGILE_PN: 150-79025; CAD_APPROVED: Yes; FPLIST: CC0402_25,CC0402_HD,0402_CC,capc0402_l; HEIGHT: 0.55MM; MFG_NAME01: MURATA; MFG_PN01: GCM155R71C104KA55D; Package Size: 0402; Package Type: ø180mm Reel PAPER; ROHS: Yes; Rated Voltage: 16V; Temp Range: -55C to +125C; Tolerance: 10%
C5203 C5210 C5244 C5248 = CAP_NP: CAP CER 1UF 25V 10% X7R 0603; AGILE_PN: 150-30185; CAD_APPROVED: Yes; FPLIST: CC0603_OV,CC0603,0603_CC; HEIGHT: 0.9mm; MFG_NAME01: WURTH ELEKTRONIK EISOS GMBH & CO. KG (ELECTRONIC & ELECTROMEHANICAL COMP); MFG_PN01: 885012206076; Package Size: 0603; Package Type: tape & reel; ROHS: Yes; Rated Voltage: 25V; Temp Range: -55C to +125C; Tolerance: 10%
C5204 C5205 C5250 C5251 = CAP_NP: CAP CER 10uF 25V 10% X7R 1206; AGILE_PN: 150-79147; CAD_APPROVED: Yes; FPLIST: CC1206_OV,CC1206,1206_CC; HEIGHT: 1.8MM; MFG_NAME01: MURATA; MFG_PN01: GRM31CR71E106KA12; ROHS: Yes; Rated Voltage: 25V; Temp Range: -55C to +125C; Tolerance: 10%
C5207-C5209 C5245-C5247 = CAP_NP: CAP CER 22uF 16V 20% X6S AEC-Q200 1206; AGILE_PN: 150-81260; CAD_APPROVED: Yes; HEIGHT: 1.8 mm; MFG_NAME01: Murata Electronics; MFG_PN01: GRT31CC81C226ME01L; Package Size: 1206 (3216 metric); Package Type: SMD/SMT; ROHS: Yes; Rated Voltage: 16V; Temp Range: -55C to +105C; Tolerance: 20%
C5211 C5249 = CAP_NP: CAP CER 0.047UF 25V 10% X7R 0603; AGILE_PN: 150-75199; CAD_APPROVED: Yes; FPLIST: CC0603_OV,CC0603,0603_CC; HEIGHT: 0.9652mm; MFG_NAME01: VENKEL COMPANY; MFG_PN01: C0603X7R250-473KNE; Package Size: 0603; Package Type: embossed tape; ROHS: Yes; Rated Voltage: 25V; Temp Range: -55C to +125C; Tolerance: 10%
L56 L57 = INDUCTOR: IND PWR 1uH@100kHz 11A 20% AEC-Q200 SMD; 3D_Mechanical_Footprint_File: http://fcl.am.freescale.net/ALLEGRO/step/ind2_sq6p9_3_sm.step; AGILE_PN: 180-81433; CAD_APPROVED: Yes; HEIGHT: 3.00MM; MFG_NAME01: Pulse Electronics; MFG_PN01: PA4341.102NLT; Package Size: 7.6 x 6.9 mm; ROHS: Yes; Temp Range: -55C to +125C
R2 = RES: RES MF 93.1K 1/10W 1% AEC-Q200 0402; AGILE_PN: 470-31058; CAD_APPROVED: Yes; FPLIST: RC0402_25,RC0402_HD,0402_CC; HEIGHT: 0.40 MM; MFG_NAME01: KOA SPEER; MFG_PN01: RK73H1ETTP9312F; ROHS: Yes; Temp Range: -55C to +155C; Tolerance: 1%
R3 = RES: RES MF 29.4K  1/10W 1% AEC-Q200 0402; AGILE_PN: 470-81707; CAD_APPROVED: Yes; FPLIST: RC0402_25,RC0402_HD,0402_CC; HEIGHT: 0.40 MM; MFG_NAME01: KOA SPEER; MFG_PN01: RK73H1ETTP2942F; ROHS: Yes; Temp Range: -55C to +155C; Tolerance: 1%
R5763 R5801 = RES: RES MF 10.0 OHM 1/16W 1% 0402; 3D_Mechanical_Footprint_File: http://fcl.am.freescale.net/ALLEGRO/step/rc0402_25.STEP; AGILE_PN: 470-76090; CAD_APPROVED: Yes; FPLIST: RC0402_25,RC0402_HD,0402_CC; HEIGHT: 0.4MM; MFG_NAME01: BOURNS; MFG_PN01: CR0402-FX-10R0GLF; ROHS: Yes; Tolerance: 1%
R5766 = RES: RES MF 20K 1/16W 1% 0402; AGILE_PN: 470-76103; CAD_APPROVED: Yes; FPLIST: RC0402_25,RC0402_HD,0402_CC; HEIGHT: 0.4MM; MFG_NAME01: WALSIN TECHNOLOGY CORP.; MFG_PN01: WR04X2002FTL; ROHS: Yes; Tolerance: 1%
R5748 R5767 R5768 = RES: RES MF 10.0K 1/16W 1% AEC-Q200 0402; AGILE_PN: 470-75416; CAD_APPROVED: Yes; FPLIST: RC0402_25,RC0402_HD,0402_CC; HEIGHT: 0.4MM; MFG_NAME01: KOA SPEER; MFG_PN01: RK73H1ETTP1002F; PRIORITY_PN: 006-00552; ROHS: Yes; ROOM: 1V5_SB; Temp Range: –55 °C to +155 °C; Tolerance: 1%
TP246 TP260 = T_POINT_TH: TEST POINT PAD 20 MILS SMT, NOT PART TO ORDER; AGILE_PN: 211-81036; CAD_APPROVED: Yes; FPLIST: tpad_020_top,tpad_020_btm_nsp; HEIGHT: 0.127MM; MFG_NAME01: NO PART ORDER; MFG_PN01: NA; ROHS: Yes
U68 U69 = AP62600SJ: IC VREG SYNC BUCK 0.6-7V 6A 4.5-18V QFN12; 3D_Mechanical_Footprint_File: http://fcl.am.freescale.net/ALLEGRO/step/qfn12_0p5_2p05x3p05mm.STEP; AGILE_PN: 315-84036; CAD_APPROVED: Yes; HEIGHT: 0.85 MM; MFG_NAME01: DIODES INC; Package Size: 2x3; ROHS: Yes; Supply Voltage: 4.5-18V
C254 = CAP_NP: CAP CER 0.01UF 50V 10% X7R 0402; AGILE_PN: 150-30114; CAD_APPROVED: Yes; FPLIST: CC0402_25,CC0402_HD,0402_CC,capc0402_l; HEIGHT: 0.55 MM; MFG_NAME01: MURATA; MFG_PN01: GRM155R71H103KA88D; ROHS: Yes; Rated Voltage: 50V; SIGNAL_MODEL: DEFAULT_CAPACITOR_10000pF_2_1; TOL: 10%; Temp Range: -55C to +125C; Tolerance: 10%; VOLTAGE: 50V
C255 C256 = CAP_NP: CAP CER 10UF 10V 10% X5R 0603; AGILE_PN: 150-78675; CAD_APPROVED: Yes; FPLIST: CC0603_OV,CC0603,0603_CC_NSP; HEIGHT: 1.016MM; MFG_NAME01: MURATA; MFG_PN01: GRM188R61A106KE69D; ROHS: Yes; Rated Voltage: 10V; Temp Range: -55C to +85C; Tolerance: 10%; VOLTAGE: 6.3V
R5747 = RES: RES MF 20K 1/16W 1% AEC-Q200 0402; AGILE_PN: 470-80743; CAD_APPROVED: Yes; FPLIST: RC0402_25,RC0402_HD,0402_CC; HEIGHT: 0.4MM; MFG_NAME01: KOA SPEER; MFG_PN01: RK73H1ETTP2002F; ROHS: Yes
U630 = MAX8902B: IC VREG LDO ADJ 0.6-5.3V 0.5A 1.7-5.5V AUTO TDFN8; 3D_Mechanical_Footprint_File: http://fcl.am.freescale.net/ALLEGRO/step/tdfn8_1p98_2p10x2p10.STEP; AGILE_PN: 315-80348; CAD_APPROVED: Yes; HEIGHT: 0.8MM; MFG_NAME01: MAXIM; MFG_PN01: MAX8902BATA/V+; ROHS: Yes; ROOM: VDD_LP_PS; VOLTAGE: 1.7-5.5V
U22 = T4240: IC MPU 64BIT T4240 1.8GHz 1.025V CRYPTO QorIQ PBGA1932; 3D_Mechanical_Footprint_File: http://fcl.am.freescale.net/ALLEGRO/step/bga1932_1mm_45x45mm.STEP; AGILE_PN: 330-77243; CAD_APPROVED: Yes; HEIGHT: 3.33 MM; MFG_NAME01: NXP SEMICONDUCTOR; Package Size: SOT1645-1; Part Number: 71F101G206X01; Product Name: (N)SOC FREESCALE:T4240NSE7TTB; ROHS: Yes; Temp Range: 0 to 105 °C
C128 C129 C138 C150 C157 C161 C165 C168 C182 C191 C192 C196 C209 C218 C246 C251 C295 C574-C585 C587 C590 C591 C593-C603 C605 C606 C612 C613 C621-C623 C625 C626 C629 C632-C634 C636 C637 C639 C643-C646 C650-C655 C657 C665 C668 C677 C678 C680 C689 C690 C692 C693 C702 C705 C708 C714 C718 C719 C727 C737 C741-C743 C752 C753 C755 C764-C766 C779 C786-C788 C796 C801 C803 C805-C813 C817-C819 C823-C825 C827-C832 C834-C836 C838 C840 C844 C846 C848-C858 C861-C866 C869 C870 C872-C876 = CAP_NP: CAP CER 0.1uF 16V 10% X7R AEC-Q200 0402; AGILE_PN: 150-79025; CAD_APPROVED: Yes; FPLIST: CC0402_25,CC0402_HD,0402_CC,capc0402_l; HEIGHT: 0.55MM; MFG_NAME01: MURATA; MFG_PN01: GCM155R71C104KA55D; Package: 0402; Package Size: 0402; Package Type: ø180mm Reel PAPER; Part Number: 4CC104B163X00; Product Name: (H)MLCC 0.1uF/16V +-10% 0402 X7R; ROHS: Yes; Rated Voltage: 16V; Temp Range: -55C to +125C; Tolerance: 10%
C120-C123 C143 C173 C205 C253 C268-C271 C546-C557 C570 C573 C588 C628 C710 C821 C822 C839 C877 C880 C1265 = CAP_NP: CAP CER 47uF 6.3V 20% X5R AEC-Q200 0805; AGILE_PN: 150-80462; CAD_APPROVED: Yes; FPLIST: CC0805_OV,CC0805,0805_CC; HEIGHT: 1.45MM; MFG_NAME01: MURATA; MFG_PN01: GRT21BR60J476ME13L; Package: 0805; Package Size: 2x1.25MM; Package Type: 0805; Part Number: 4CC476D631X00; Product Name: (H)MLCC 47uF/6.3V +-20% 0805 X5R; ROHS: Yes; Rated Voltage: 6.3V; Temp Range: -55C to +85C; Tolerance: 20%
C250 C252 C566-C569 C571 C572 C728 C782 C878 C879 = CAP_NP: CAP CER 10UF 10V 10% X5R 0603; AGILE_PN: 150-78675; CAD_APPROVED: Yes; FPLIST: CC0603_OV,CC0603,0603_CC_NSP; HEIGHT: 1.016MM; MFG_NAME01: MURATA; MFG_PN01: GRM188R61A106KE69D; Package: 0805; Part Number: 4CC106D101X00; Product Name: (H)MLCC 10uF/10V +/-10% 0805 X5R; ROHS: Yes; Rated Voltage: 10V; Temp Range: -55C to +85C; Tolerance: 10%
CT24 CT29 CT41 = CAP_POL: CAP TANT ESR=0.009 OHMS 470UF 2.5V 20% -- 7343-18; AGILE_PN: 150-78476; ASSY_OPT: DNP; CAD_APPROVED: Yes; HEIGHT: 1.9MM; MFG_NAME01: SANYO; MFG_PN01: 2R5TPE470M9; Package: SMD; Part Number: 4CP477D021X00; Product Name: KO CAP 470uF/2.5V KEMET:T520V477M2R5ATE009; ROHS: Yes; Rated Voltage: 2.5V; Tolerance: 20%
CT30 CT32 CT40 CT42-CT48 = CAP_POL: CAP TANT ESR=0.009 OHMS 470UF 2.5V 20% -- 7343-18; AGILE_PN: 150-78476; CAD_APPROVED: Yes; HEIGHT: 1.9MM; MFG_NAME01: SANYO; MFG_PN01: 2R5TPE470M9; Package: SMD; Part Number: 4CP477D021X00; Product Name: KO CAP 470uF/2.5V KEMET:T520V477M2R5ATE009; ROHS: Yes; Rated Voltage: 2.5V; Tolerance: 20%
FB9-FB12 FB16-FB20 FB24-FB26 FB47-FB56 = BEAD_FERRITE: IND FER BEAD 120OHM@100MHZ 2A 25% 0603; AGILE_PN: 180-30008; CAD_APPROVED: Yes; FPLIST: IND_0603,0603_CC; HEIGHT: 0.95MM; MFG_NAME01: MURATA; MFG_PN01: BLM18PG121SH1; ROHS: Yes
R270 R714 R722 = RES: RES MF 330 OHM 1/16W 5% 0402; AGILE_PN: 470-75613; CAD_APPROVED: Yes; FPLIST: RC0402_25,RC0402_HD,0402_CC; HEIGHT: 0.41mm; MFG_NAME01: BOURNS; MFG_PN01: CR0402-JW-331GLF; Package: 0402; Part Number: 4RC3301B11X00; Product Name: (H)RES 330E 1/16W 0402 1% PBFREE; ROHS: Yes; Tolerance: 5%
R273 = RES: RES MF ZERO OHM 1/10W AEC-Q200 0603; AGILE_PN: 470-82905; ASSY_OPT: DNP; CAD_APPROVED: Yes; FPLIST: RC0603_OV,RC0603,0603_CC; HEIGHT: 0.55 MM; MFG_NAME01: YAGEO AMERICA; MFG_PN01: AC0603FR-070RL; Package: 0603; Part Number: 4RC0000C51X00; Product Name: (H)RES 0E 1/10W 0603 5% PBFREE; ROHS: Yes; Temp Range: -55 °C to +155 °C
R278 R285 R712 = RES: RES MF ZERO OHM 1/10W AEC-Q200 0603; AGILE_PN: 470-82905; CAD_APPROVED: Yes; FPLIST: RC0603_OV,RC0603,0603_CC; HEIGHT: 0.55 MM; MFG_NAME01: YAGEO AMERICA; MFG_PN01: AC0603FR-070RL; Package: 0603; Part Number: 4RC0000C51X00; Product Name: (H)RES 0E 1/10W 0603 5% PBFREE; ROHS: Yes; Temp Range: -55 °C to +155 °C
C133-C136 C260-C263 = CAP_NP: CAP CER 4.7uF 10V 10% X5R 0603; AGILE_PN: 150-79199; CAD_APPROVED: Yes; FPLIST: CC0603_OV,CC0603,0603_CC; HEIGHT: 0.9MM; MFG_NAME01: TDK; MFG_PN01: C1608X5R1A475K080AC; Package: 0603; Package Size: 0603; Part Number: 4CC475C101X00; Product Name: (N)(H)MLCC 4.7uF/10V +-10% 0603 X5R; ROHS: Yes; Rated Voltage: 10V; Temp Range: -55C to +85C; Tolerance: 10%
C607-C611 C638 C715 C800 C802 = CAP_NP: CAP CER 1uF 10V 10% X7S 0402; AGILE_PN: 150-80357; CAD_APPROVED: Yes; FPLIST: CC0402_25,CC0402_HD,0402_CC,capc0402_l; HEIGHT: 0.6MM; MFG_NAME01: MURATA; MFG_PN01: GRM155C71A105KE11D; Package: 0402; Package Size: 0402; Part Number: 4CC105B101X00; Product Name: (H)MLCC 1uF/10V +-10% 0402 X5R; ROHS: Yes; Rated Voltage: 10V; Temp Range: -55C to +125C; Tolerance: 10%
C258 C274 C283 C284 C562 C564 C616-C619 C627 C709 C833 C837 C841-C843 C845 C847 = CAP_NP: CAP CER 3300pF 50V 10% X7R AEC-Q200 0402; AGILE_PN: 150-79050; CAD_APPROVED: Yes; FPLIST: CC0402_25,CC0402_HD,0402_CC,capc0402_l; HEIGHT: 0.55MM; MFG_NAME01: TDK; MFG_PN01: CGA2B2X7R1H332K050BA; Package: 0402; Package Size: 0402; Package Type: Paper Tape; Part Number: 4CC332B501X00; Product Name: (H)MLCC 3300pF/50V +-10% 0402 X7R; ROHS: Yes; Rated Voltage: 50V; Temp Range: -55C to +125C; Tolerance: 10%
R175 R178 R179 R182 R313 R314 R317 R319 = RES: RES MF 0.33 OHM 1/16W 1% AEC-Q200 0402; AGILE_PN: 470-82347; CAD_APPROVED: Yes; FPLIST: RC0402_25,RC0402_HD,0402_CC; HEIGHT: 0.4MM; MFG_NAME01: YAGEO AMERICA; MFG_PN01: RL0402FR-070R33L; Package: 0402; Part Number: 4RC047AB11X00; Product Name: (H)RES 0.47E 1/16W 0402 1% PBFREE; ROHS: Yes; Temp Range: -55C to 155C; Tolerance: 1%
R176 R177 R180 R181 R311 R312 R315 R316 = RES: RES MF ZERO OHM 1/10W -- 0402; AGILE_PN: 470-79965; CAD_APPROVED: Yes; FPLIST: RC0402_25,RC0402_HD,RC0402_X2,0402_CC,RC0402_X3; HEIGHT: 0.4MM; MFG_NAME01: PANASONIC; MFG_PN01: ERJ-2GE0R00X; Package: 0402; Part Number: 4RC0000B51X00; Product Name: (H)RES 0E 1/16W 0402 5% PBFREE; ROHS: Yes; Temp Range: –55 °C to +155 °C
R685-R687 R689-R691 R708 R769 R770 = RES: RES MF 5.1 OHM 1/16W 1% AEC-Q200 0402; AGILE_PN: 470-80808; CAD_APPROVED: Yes; FPLIST: RC0402_25,RC0402_HD,0402_CC; HEIGHT: 0.4MM; MFG_NAME01: VISHAY INTERTECHNOLOGY; MFG_PN01: CRCW04025R10FKED; Package: 0402; Part Number: 4RC0510B11X00; Product Name: (H)RES 5.1E 1/16W 0402 1%; ROHS: Yes
C259 C265 C273 C275 C280-C282 C285 C286 C563 C565 C604 C614 C620 C624 C691 C716 C859 C867 = CAP_NP: CAP CER 2.2uF 6.3V 10% X5R 0402; AGILE_PN: 150-79454; CAD_APPROVED: Yes; FPLIST: CC0402_25,CC0402_HD,0402_CC,capc0402_l; HEIGHT: 0.55MM; MFG_NAME01: MURATA; MFG_PN01: GRM155R60J225KE01D; Package: 0402; Part Number: 4CC225B101X00; Product Name: MLCC 2.2u/10V +-20% 0402 X5R; ROHS: Yes; Rated Voltage: 6.3V; Temp Range: -55C to +85C; Tolerance: 10%
C288 C860 C868 = CAP_NP: CAP CER 22uF 16V 20% X6S AEC-Q200 1206; AGILE_PN: 150-81260; CAD_APPROVED: Yes; HEIGHT: 1.8 mm; MFG_NAME01: Murata Electronics; MFG_PN01: GRT31CC81C226ME01L; Package: 1206; Package Size: 1206 (3216 metric); Package Type: SMD/SMT; Part Number: 4CC226E161X00; Product Name: (H)MLCC 22uF/16V +-10% 1206 X5R; ROHS: Yes; Rated Voltage: 16V; Temp Range: -55C to +105C; Tolerance: 20%
C630 C631 C640-C642 C647-C649 C658-C664 C669-C676 C681-C688 C694-C701 C706 C707 C711-C713 C720-C726 C729-C736 C744-C751 C756-C763 C771-C778 C789-C795 C804 C987 = CAP_NP: CAP CER 1uF 10V 10% X7S 0402; AGILE_PN: 150-80357; CAD_APPROVED: Yes; FPLIST: CC0402_25,CC0402_HD,0402_CC,capc0402_l; HEIGHT: 0.6MM; MFG_NAME01: MURATA; MFG_PN01: GRM155C71A105KE11D; Package: 0402; Package Size: 0402; Part Number: 4CC475B632X00; Product Name: (H)MLCC 4.7uF/6.3V +-20% 0402 X5R; ROHS: Yes; Rated Voltage: 10V; Temp Range: -55C to +125C; Tolerance: 10%
R696 R699 R706 R707 R709 R710 R716 R725 = RES: RES MF 10.0 OHM 1/16W 1% 0402; 3D_Mechanical_Footprint_File: http://fcl.am.freescale.net/ALLEGRO/step/rc0402_25.STEP; AGILE_PN: 470-76090; CAD_APPROVED: Yes; FPLIST: RC0402_25,RC0402_HD,0402_CC,rc0402_ghwe; HEIGHT: 0.4MM; MFG_NAME01: BOURNS; MFG_PN01: CR0402-FX-10R0GLF; Package: 0402; Part Number: 4RC1000B11X00; Product Name: (H)RES 10E 1/16W 0402 1% PBFREE; ROHS: Yes; Tolerance: 1%

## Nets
2V5: C805.1 C806.1 C848.1 C1265.1 C5245.1 C5246.1 C5247.1 C5248.2 L57.2 R2.1 U22.L14(LVDD1) U22.R16(LVDD2) U22.R17(LVDD3) ; also on sheet 24 38 45
AGND_SRDS1_PLL1: C263.2 C271.2 C841.2 R316.1 U22.L18(AGND_SD1_PLL1)
AGND_SRDS1_PLL2: C262.2 C270.2 C842.2 R315.1 U22.L20(AGND_SD1_PLL2)
AGND_SRDS2_PLL1: C261.2 C269.2 C845.2 R312.1 U22.L25(AGND_SD2_PLL1)
AGND_SRDS2_PLL2: C260.2 C268.2 C843.2 R311.1 U22.L27(AGND_SD2_PLL2)
AGND_SRDS3_PLL1: C123.2 C136.2 C617.2 R181.1 U22.AP21(AGND_SD3_PLL1)
AGND_SRDS3_PLL2: C122.2 C135.2 C616.2 R176.1 U22.AP23(AGND_SD3_PLL2)
AGND_SRDS4_PLL1: C121.2 C134.2 C618.2 R180.1 U22.AP28(AGND_SD4_PLL1)
AGND_SRDS4_PLL2: C120.2 C133.2 C619.2 R177.1 U22.AP30(AGND_SD4_PLL2)
AVDD_CGA1: C567.1 C607.1 R686.2 U22.AP13(AVDD_CGA1)
AVDD_CGA2: C568.1 C608.1 R687.2 U22.AR13(AVDD_CGA2)
AVDD_CGA3: C569.1 C609.1 R689.2 U22.AR14(AVDD_CGA3)
AVDD_CGB1: C572.1 C611.1 R691.2 U22.AR16(AVDD_CGB1)
AVDD_CGB2: C571.1 C610.1 R690.2 U22.AR15(AVDD_CGB2)
AVDD_DDR1: C800.1 C878.1 R770.2 U22.T13(AVDD_D1)
AVDD_DDR2: C566.1 C638.1 R685.2 U22.AJ13(AVDD_D2)
AVDD_DDR3: C715.1 C728.1 R708.2 U22.AC32(AVDD_D3)
AVDD_PLAT: C802.1 C879.1 R769.2 U22.T28(AVDD_PLAT)
AVDD_SRDS1_PLL1: C263.1 C271.1 C841.1 R317.1 U22.L17(AVDD_SD1_PLL1)
AVDD_SRDS1_PLL2: C262.1 C270.1 C842.1 R314.1 U22.L21(AVDD_SD1_PLL2)
AVDD_SRDS2_PLL1: C261.1 C269.1 C845.1 R313.1 U22.L24(AVDD_SD2_PLL1)
AVDD_SRDS2_PLL2: C260.1 C268.1 C843.1 R319.1 U22.L28(AVDD_SD2_PLL2)
AVDD_SRDS3_PLL1: C123.1 C136.1 C617.1 R182.1 U22.AP20(AVDD_SD3_PLL1)
AVDD_SRDS3_PLL2: C122.1 C135.1 C616.1 R175.1 U22.AP24(AVDD_SD3_PLL2)
AVDD_SRDS4_PLL1: C121.1 C134.1 C618.1 R179.1 U22.AP27(AVDD_SD4_PLL1)
AVDD_SRDS4_PLL2: C120.1 C133.1 C619.1 R178.1 U22.AP31(AVDD_SD4_PLL2)
GND: C128.2 C129.2 C138.2 C143.2 C150.2 C157.2 C161.2 C165.2 C168.2 C173.2 C182.2 C191.2 C192.2 C196.2 C205.2 C209.2 C218.2 C246.2 C250.2 C251.2 C252.2 C253.2 C255.2 C256.2 C258.2 C259.2 C265.2 C273.2 C274.2 C275.2 C280.2 C281.2 C282.2 C283.2 C284.2 C285.2 C286.2 C288.2 C295.2 C546.2 C547.2 C548.2 C549.2 C550.2 C551.2 C552.2 C553.2 C554.2 C555.2 C556.2 C557.2 C562.2 C563.2 C564.2 C565.2 C566.2 C567.2 C568.2 C569.2 C570.2 C571.2 C572.2 C573.2 C574.2 C575.2 C576.2 C577.2 C578.2 C579.2 C580.2 C581.2 C582.2 C583.2 C584.2 C585.2 C587.2 C588.2 C590.2 C591.2 C593.2 C594.2 C595.2 C596.2 C597.2 C598.2 C599.2 C600.2 C601.2 C602.2 C603.2 C604.2 C605.2 C606.2 C607.2 C608.2 C609.2 C610.2 C611.2 C612.2 C613.2 C614.2 C620.2 C621.2 C622.2 C623.2 C624.2 C625.2 C626.2 C627.2 C628.2 C629.2 C630.2 C631.2 C632.2 C633.2 C634.2 C636.2 C637.2 C638.2 C639.2 C640.2 C641.2 C642.2 C643.2 C644.2 C645.2 C646.2 C647.2 C648.2 C649.2 C650.2 C651.2 C652.2 C653.2 C654.2 C655.2 C657.2 C658.2 C659.2 C660.2 C661.2 C662.2 C663.2 C664.2 C665.2 C668.2 C669.2 C670.2 C671.2 C672.2 C673.2 C674.2 C675.2 C676.2 C677.2 C678.2 C680.2 C681.2 C682.2 C683.2 C684.2 C685.2 C686.2 C687.2 C688.2 C689.2 C690.2 C691.2 C692.2 C693.2 C694.2 C695.2 C696.2 C697.2 C698.2 C699.2 C700.2 C701.2 C702.2 C705.2 C706.2 C707.2 C708.2 C709.2 C710.2 C711.2 C712.2 C713.2 C714.2 C715.2 C716.2 C718.2 C719.2 C720.2 C721.2 C722.2 C723.2 C724.2 C725.2 C726.2 C727.2 C728.2 C729.2 C730.2 C731.2 C732.2 C733.2 C734.2 C735.2 C736.2 C737.2 C741.2 C742.2 C743.2 C744.2 C745.2 C746.2 C747.2 C748.2 C749.2 C750.2 C751.2 C752.2 C753.2 C755.2 C756.2 C757.2 C758.2 C759.2 C760.2 C761.2 C762.2 C763.2 C764.2 C765.2 C766.2 C771.2 C772.2 C773.2 C774.2 C775.2 C776.2 C777.2 C778.2 C779.2 C782.2 C786.2 C787.2 C788.2 C789.2 C790.2 C791.2 C792.2 C793.2 C794.2 C795.2 C796.2 C800.2 C801.2 C802.2 C803.2 C804.2 C805.2 C806.2 C807.2 C808.2 C809.2 C810.2 C811.2 C812.2 C813.2 C817.2 C818.2 C819.2 C821.2 C822.2 C823.2 C824.2 C825.2 C827.2 C828.2 C829.2 C830.2 C831.2 C832.2 C833.2 C834.2 C835.2 C836.2 C837.2 C838.2 C839.2 C840.2 C844.2 C846.2 C847.2 C848.2 C849.2 C850.2 C851.2 C852.2 C853.2 C854.2 C855.2 C856.2 C857.2 C858.2 C859.2 C860.2 C861.2 C862.2 C863.2 C864.2 C865.2 C866.2 C867.2 C868.2 C869.2 C870.2 C872.2 C873.2 C874.2 C875.2 C876.2 C877.2 C878.2 C879.2 C880.2 C987.2 C1265.2 C5203.1 C5204.2 C5205.2 C5206.1 C5207.2 C5208.2 C5209.2 C5210.1 C5211.2 C5244.1 C5245.2 C5246.2 C5247.2 C5248.1 C5249.2 C5250.2 C5251.2 C5252.1 CT24.2 CT29.2 CT30.2 CT32.2 CT40.2 CT41.2 CT42.2 CT43.2 CT44.2 CT45.2 CT46.2 CT47.2 CT48.2 R3.2 R176.2 R177.2 R180.2 R181.2 R270.2 R311.2 R312.2 R315.2 R316.2 R714.2 R722.2 R5748.2 R5767.2 R5768.2 U68.1(PGND) U68.11(GND) U69.1(PGND) U69.11(GND) U630.2(GND) U630.4(GS) U630.9(EP) ; also on sheet 6 7 8 9 10 11 12 13 14 22 24 25 27 28 29 30 31 32 33 34 35 36 37 38 39 40 41 42 43 44 45 46 47 48 49 50 51 52 53 54
P1V8_AVDD: FB26.2 R685.1 R686.1 R687.1 R689.1 R690.1 R691.1 R708.1 R769.1 R770.1
SVDD: CT32.1 CT44.1 FB16.1 FB17.1 FB18.1 FB19.1 FB51.1 FB52.1 FB53.1 FB54.1 ; also on sheet 14
VCC_3.3: C256.1 FB56.2 U630.1(IN) ; also on sheet 6 12 13 24 25 31 32 33 36 39 40 41 42 43 44 47 48 49 50 51 53
VCC_12: C5204.1 C5205.1 C5206.2 C5250.1 C5251.1 C5252.2 U68.2(VIN) U69.2(VIN) ; also on sheet 6 11 14 47 48 53
VCC_DVDD: C827.1 C828.1 C880.1 FB24.1 U22.R14(DVDD1) U22.R15(DVDD2) ; also on sheet 27 50 52
VDD: C546.1 C547.1 C548.1 C549.1 C550.1 C551.1 C552.1 C553.1 C554.1 C555.1 C556.1 C557.1 C630.1 C631.1 C640.1 C641.1 C642.1 C647.1 C648.1 C649.1 C658.1 C659.1 C660.1 C661.1 C662.1 C663.1 C664.1 C669.1 C670.1 C671.1 C672.1 C673.1 C674.1 C675.1 C676.1 C681.1 C682.1 C683.1 C684.1 C685.1 C686.1 C687.1 C688.1 C694.1 C695.1 C696.1 C697.1 C698.1 C699.1 C700.1 C701.1 C706.1 C707.1 C711.1 C712.1 C713.1 C720.1 C721.1 C722.1 C723.1 C724.1 C725.1 C726.1 C729.1 C730.1 C731.1 C732.1 C733.1 C734.1 C735.1 C736.1 C744.1 C745.1 C746.1 C747.1 C748.1 C749.1 C750.1 C751.1 C756.1 C757.1 C758.1 C759.1 C760.1 C761.1 C762.1 C763.1 C771.1 C772.1 C773.1 C774.1 C775.1 C776.1 C777.1 C778.1 C789.1 C790.1 C791.1 C792.1 C793.1 C794.1 C795.1 C804.1 C987.1 FB20.2 R285.2 U22.AA17(VDD30) U22.AA19(VDD31) U22.AA21(VDD32) U22.AA23(VDD33) U22.AA25(VDD34) U22.AA27(VDD35) U22.AA29(VDD36) U22.AB16(VDD37) U22.AB18(VDD38) U22.AB20(VDD39) U22.AB22(VDD40) U22.AB24(VDD41) U22.AB26(VDD42) U22.AB28(VDD43) U22.AC17(VDD44) U22.AC19(VDD45) U22.AC21(VDD46) U22.AC23(VDD47) U22.AC25(VDD48) U22.AC27(VDD49) U22.AC29(VDD50) U22.AD16(VDD51) U22.AD18(VDD52) U22.AD20(VDD53) U22.AD22(VDD54) U22.AD24(VDD55) U22.AD26(VDD56) U22.AD28(VDD57) U22.AE17(VDD58) U22.AE19(VDD59) U22.AE21(VDD60) U22.AE23(VDD61) U22.AE25(VDD62) U22.AE27(VDD63) U22.AE29(VDD64) U22.AF16(VDD65) U22.AF18(VDD66) U22.AF20(VDD67) U22.AF22(VDD68) U22.AF24(VDD69) U22.AF26(VDD70) U22.AF28(VDD71) U22.AG17(VDD72) U22.AG19(VDD73) U22.AG21(VDD74) U22.AG23(VDD75) U22.AG25(VDD76) U22.AG27(VDD77) U22.AG29(VDD78) U22.AH16(VDD79) U22.AH18(VDD80) U22.AH20(VDD81) U22.AH22(VDD82) U22.AH24(VDD83) U22.AH26(VDD84) U22.AH28(VDD85) U22.AJ17(VDD86) U22.AJ19(VDD87) U22.AJ21(VDD88) U22.AK16(VDD89) U22.AK18(VDD90) U22.AK20(VDD91) U22.T16(VDD01) U22.U17(VDD02) U22.U19(VDD03) U22.U21(VDD04) U22.U23(VDD05) U22.U25(VDD06) U22.U27(VDD07) U22.U29(VDD08) U22.V16(VDD09) U22.V18(VDD10) U22.V20(VDD11) U22.V22(VDD12) U22.V24(VDD13) U22.V26(VDD14) U22.V28(VDD15) U22.W17(VDD16) U22.W19(VDD17) U22.W21(VDD18) U22.W23(VDD19) U22.W25(VDD20) U22.W27(VDD21) U22.W29(VDD22) U22.Y16(VDD23) U22.Y18(VDD24) U22.Y20(VDD25) U22.Y22(VDD26) U22.Y24(VDD27) U22.Y26(VDD28) U22.Y28(VDD29) ; also on sheet 12
VDD_FA_VDD: R722.1 U22.R33(FA_VL)
VDD_LP: C252.1 C831.1 R285.1 U22.R28(VDD_LP) ; also on sheet 27
VDD_OVDD_P1V8: C629.1 C737.1 C752.1 C764.1 C779.1 C796.1 C819.1 C821.1 C832.1 FB25.1 U22.AA30(OVDD7) U22.AK14(OVDD8) U22.R30(OVDD1) U22.T30(OVDD2) U22.U30(OVDD3) U22.V30(OVDD4) U22.W30(OVDD5) U22.Y30(OVDD6)
VDD_S1VDD: C284.1 C285.1 C286.1 C807.1 C808.1 C809.1 C810.1 C811.1 C829.1 C830.1 FB18.2 FB19.2 U22.N17(S1VDD1) U22.P20(S1VDD2) U22.P22(S1VDD3) U22.T19(S1VDD4) U22.T20(S1VDD5) U22.T21(S1VDD6) U22.T22(S1VDD7) ; also on sheet 37
VDD_S2VDD: C281.1 C282.1 C283.1 C801.1 C812.1 C813.1 C818.1 C824.1 C835.1 FB16.2 FB17.2 U22.P23(S2VDD1) U22.P25(S2VDD2) U22.T23(S2VDD3) U22.T24(S2VDD4) U22.T25(S2VDD5) U22.T26(S2VDD6) ; also on sheet 37
VDD_S3VDD: C626.1 C632.1 C636.1 C643.1 C644.1 C650.1 C651.1 C691.1 C709.1 C716.1 FB53.2 FB54.2 U22.AJ22(S3VDD1) U22.AJ23(S3VDD2) U22.AJ24(S3VDD3) U22.AJ25(S3VDD4) U22.AL23(S3VDD5) U22.AL25(S3VDD6) U22.AM20(S3VDD7) ; also on sheet 46
VDD_S4VDD: C614.1 C624.1 C625.1 C627.1 C633.1 C645.1 C652.1 C654.1 C655.1 FB51.2 FB52.2 U22.AJ26(S4VDD1) U22.AJ27(S4VDD2) U22.AJ28(S4VDD3) U22.AJ29(S4VDD4) U22.AL26(S4VDD5) U22.AL28(S4VDD6) ; also on sheet 46
VDD_SENSE_N: R696.2 R706.2 R707.2 R716.2 ; also on sheet 12
VDD_SENSE_P: R699.2 R709.2 R710.2 R725.2 ; also on sheet 12
VDD_TH_VDD: C782.1 C788.1 R712.1 U22.V32(TH_VDD)
VDD_X1VDD: C258.1 C259.1 C265.1 C849.1 C850.1 C851.1 C852.1 C853.1 C854.1 C855.1 C856.1 FB9.1 FB10.1 U22.K15(X1VDD1) U22.K16(X1VDD2) U22.K17(X1VDD3) U22.K18(X1VDD4) U22.K19(X1VDD5) U22.K20(X1VDD6) U22.K21(X1VDD7) U22.K22(X1VDD8) ; also on sheet 37
VDD_X2VDD: C273.1 C274.1 C275.1 C844.1 C846.1 C858.1 C861.1 C862.1 C863.1 C864.1 C865.1 C866.1 FB11.1 FB12.1 U22.K23(X2VDD1) U22.K24(X2VDD2) U22.K25(X2VDD3) U22.K26(X2VDD4) U22.K27(X2VDD5) U22.K28(X2VDD6) U22.K29(X2VDD7) U22.K30(X2VDD8) U22.M30(X2VDD9) ; also on sheet 37
VDD_X3VDD: C562.1 C563.1 C593.1 C595.1 C596.1 C597.1 C606.1 C612.1 C613.1 C620.1 FB47.1 FB48.1 U22.AR18(X3VDD1) U22.AR19(X3VDD2) U22.AR20(X3VDD3) U22.AR21(X3VDD4) U22.AR22(X3VDD5) U22.AR23(X3VDD6) U22.AR24(X3VDD7) U22.AR25(X3VDD8) ; also on sheet 46
VDD_X4VDD: C564.1 C565.1 C598.1 C599.1 C600.1 C601.1 C602.1 C603.1 C604.1 C605.1 C621.1 FB49.1 FB50.1 U22.AN33(X4VDD1) U22.AR26(X4VDD2) U22.AR27(X4VDD3) U22.AR28(X4VDD4) U22.AR29(X4VDD5) U22.AR30(X4VDD6) U22.AR31(X4VDD7) U22.AR32(X4VDD8) U22.AR33(X4VDD9) ; also on sheet 46
GVDD: C128.1 C129.1 C138.1 C143.1 C150.1 C157.1 C161.1 C165.1 C168.1 C173.1 C182.1 C191.1 C192.1 C196.1 C205.1 C209.1 C218.1 C246.1 C251.1 C253.1 C295.1 C570.1 C573.1 C574.1 C575.1 C576.1 C577.1 C578.1 C579.1 C580.1 C581.1 C582.1 C583.1 C584.1 C585.1 C587.1 C588.1 C590.1 C591.1 C594.1 C622.1 C623.1 C628.1 C634.1 C637.1 C639.1 C646.1 C653.1 C657.1 C665.1 C668.1 C677.1 C678.1 C680.1 C689.1 C690.1 C692.1 C693.1 C702.1 C705.1 C708.1 C710.1 C714.1 C718.1 C719.1 C727.1 C741.1 C742.1 C743.1 C753.1 C755.1 C765.1 C766.1 C786.1 C787.1 C803.1 C817.1 C822.1 C823.1 C836.1 C839.1 C857.1 C869.1 C870.1 C872.1 C873.1 C874.1 C875.1 C876.1 C877.1 CT24.1 CT29.1 CT41.1 CT42.1 CT43.1 CT45.1 CT46.1 CT47.1 CT48.1 U22.A2(G1VDD01) U22.A6(G1VDD02) U22.A9(G1VDD03) U22.AA15(G1VDD21) U22.AB1(G1VDD22) U22.AB15(G1VDD23) U22.AB30(G3VDD03) U22.AB43(G3VDD04) U22.AC15(G2VDD01) U22.AC30(G3VDD05) U22.AD2(G1VDD24) U22.AD15(G2VDD02) U22.AD30(G3VDD06) U22.AD44(G3VDD07) U22.AE15(G2VDD03) U22.AE30(G3VDD08) U22.AF1(G1VDD25) U22.AF2(G1VDD26) U22.AF15(G2VDD04) U22.AF30(G3VDD09) U22.AF43(G3VDD10) U22.AG1(G2VDD05) U22.AG15(G2VDD06) U22.AG30(G3VDD11) U22.AH15(G2VDD07) U22.AH30(G3VDD12) U22.AH44(G3VDD13) U22.AJ2(G2VDD08) U22.AJ15(G2VDD09) U22.AK43(G3VDD14) U22.AL1(G2VDD10) U22.AM44(G3VDD15) U22.AN2(G2VDD11) U22.AP43(G3VDD16) U22.AR1(G2VDD12) U22.AT44(G3VDD17) U22.AU2(G2VDD13) U22.AV43(G3VDD18) U22.AW1(G2VDD14) U22.AY44(G3VDD19) U22.B1(G1VDD04) U22.B4(G1VDD05) U22.B9(G1VDD06) U22.BA2(G2VDD15) U22.BB43(G3VDD20) U22.BC1(G2VDD16) U22.BC4(G2VDD17) U22.BC8(G2VDD18) U22.BC12(G2VDD19) U22.BC16(G2VDD20) U22.BC37(G3VDD21) U22.BC41(G3VDD22) U22.BC44(G3VDD23) U22.BD2(G2VDD21) U22.BD6(G2VDD22) U22.BD10(G2VDD23) U22.BD14(G2VDD24) U22.BD17(G2VDD25) U22.BD35(G3VDD24) U22.BD39(G3VDD25) U22.BD43(G3VDD26) U22.D2(G1VDD07) U22.F1(G1VDD08) U22.H2(G1VDD09) U22.K1(G1VDD10) U22.M2(G1VDD11) U22.P1(G1VDD12) U22.T2(G1VDD13) U22.T15(G1VDD14) U22.U15(G1VDD15) U22.V1(G1VDD16) U22.V15(G1VDD17) U22.W15(G1VDD18) U22.Y2(G1VDD19) U22.Y15(G1VDD20) U22.Y43(G3VDD01) U22.Y44(G3VDD02) ; also on sheet 11 13 28 29 30 31 32 33
OVDD: FB24.2 FB25.2 FB26.1 FB55.2 R712.2 ; also on sheet 10 11 24 25 27 34 35 36
PHY_1V8: C5207.1 C5208.1 C5209.1 C5210.2 L56.2 R5766.2 ; also on sheet 42 43
POVDD: C250.1 C254.1 C255.1 R278.2 R5747.1 U630.8(OUT)
PROG_MTR: R273.1 R714.1 U22.T29(PROG_MTR)
PROG_SFP: C825.1 R270.1 R273.2 R278.1 U22.R29(PROG_SFP)
PS_2V5_EN: TP260.1(TP) U68.3(EN) ; also on sheet 8
PS_2V5_PG: U68.6(PG) ; also on sheet 8
PS_PHY_1V8_EN: TP246.1(TP) U69.3(EN) ; also on sheet 8
PS_PHY_1V8_PG: U69.6(PG) ; also on sheet 8
PS_POVDD_EN: R5768.1 U630.3(EN) ; also on sheet 8
PS_POVDD_PG: U630.5(~{POK}) ; also on sheet 8
SENSEGND_CA_S_N: R716.1 U22.R13(SENSEGND_CA)
SENSEGND_CB_S_N: R696.1 U22.AM17(SENSEGND_CB)
SENSEGND_CC_S_N: R707.1 U22.AA33(SENSEGND_CC)
SENSEGND_PL_S_N: R706.1 U22.AA32(SENSEGND_PL)
SENSEVDD_CA_S_P: R725.1 U22.R12(SENSEVDD_CA)
SENSEVDD_CB_S_P: R699.1 U22.AM16(SENSEVDD_CB)
SENSEVDD_CC_S_P: R710.1 U22.Y33(SENSEVDD_CC)
SENSEVDD_PL_S_P: R709.1 U22.Y32(SENSEVDD_PL)
USB_HVDD: C840.1 C847.1 C859.1 C860.1 FB56.1 U22.K32(USB_HVDD1) U22.N32(USB_HVDD2)
USB_OVDD: C833.1 C834.1 C867.1 C868.1 FB55.1 U22.P31(USB_OVDD1) U22.P32(USB_OVDD2)
USB_SVDD: C280.1 C288.1 C837.1 C838.1 FB20.1 U22.P29(USB_SVDD1) U22.P30(USB_SVDD2)
XVDD: CT30.1 CT40.1 FB9.2 FB10.2 FB11.2 FB12.2 FB47.2 FB48.2 FB49.2 FB50.2 R175.2 R178.2 R179.2 R182.2 R313.2 R314.2 R317.2 R319.2 ; also on sheet 14
N31888256: C5244.2 U68.4(MODE) U68.9(VCC)
N31888261: C5243.1 U68.7(BST)
N31888263: C5243.2 R5801.1
N31888274: L57.1 R5801.2 U68.8(SW)
N31888295: R2.2 R3.1 U68.12(FB)
N31888301: C5249.1 U68.10(SS/TR)
N32122553: C254.2 U630.7(BYP)
N32122566: R5747.2 R5748.1 U630.6(FB)
N32123048: C5203.2 U69.4(MODE) U69.9(VCC)
N32123083: C5202.1 U69.7(BST)
N32123087: C5202.2 R5763.1
N32123169: L56.1 R5763.2 U69.8(SW)
N32123255: R5766.1 R5767.1 U69.12(FB)
N32123323: C5211.1 U69.10(SS/TR)

Not connected (* = marked no-connect by the designer): U68 5(FSEL)*; U69 5(FSEL)*

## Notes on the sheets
sheet 15
- 2V5 & PHY 1V8 POWER
- 2V5:   2.50V
             6A (max)
- Rx
- (>1.2V)
- Ry
- CONFIG
  ========================
  MODE = VCC (Forced PWM)
  FSEL = OPEN (800kHz)
  VOUT = 0.6*(Rx/Ry+1)
       = 2.500 V
- PHY_1V8:   1.80V
             6A (max)
- Rx
- (>1.2V)
- Ry
- CONFIG
  ========================
  MODE = VCC (Forced PWM)
  FSEL = OPEN (800kHz)
  VOUT = 0.6*(Rx/Ry+1)
       = 1.800 V
sheet 16
- MISC POWER
- POVDD: 1.80V @ 0.5A (max)
      Only on for fuse programming.
- Rx
- (>1.2V)
- Ry
- CONFIG
  ========================
  MODE = VCC (Forced PWM)
  FSEL = OPEN (800kHz)
  VOUT = 0.6*(Rx/Ry+1)
       = 1.80 V
sheet 18
- T4240 VDD/CORE POWER
- Place close to CPU
sheet 19
- T4240 SVDD / XVDD POWER
- VDD_S1VDD : 570mA
- VDD_X1VDD : 900mA
- VDD_S2VDD : 570mA
- VDD_X2VDD : 900mA
- VDD_S3VDD : 570mA
- VDD_X3VDD : 900mA
- VDD_S4VDD : 570mA
- VDD_X4VDD : 900mA
- NOTE: Power supplied by paralleled
             filters to lower I-R drop.
sheet 20
- T4240 GVDD / Other Power
- 0.6A
- 0.15A
- 0.35A
sheet 21
- T4240 PLL Filters
- Assure for each power/GND pair that
  0.33 ohm and  0 ohm resistor are
  close by each other and the ground
  point of 0 ohm is close by both.
- 17mA
- 44mA
- 17mA
- 44mA
- 17mA
- 44mA
- 17mA
- 44mA
- 17mA
- 44mA
- 17mA
- 44mA
- 28mA
- 44mA
- 28mA
- 44mA
- 28mA
